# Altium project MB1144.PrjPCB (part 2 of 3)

## Sheet LCD_Glass.SchDoc: LCD_Glass
size A3; DocumentNumber: 6; Revision: C-02; SheetNumber: 6; SheetTotal: 26; PageSetup: Record=PageOptions¦CenterHorizontal=True¦CenterVertical=True¦PrintScale=1.04¦XCorrection=1.00¦YCorrection=1.00¦PrintKind=1¦BorderSize=5000000¦LeftOffset=0¦BottomOffset=0¦Orientation=2¦PaperLength=1000¦PaperWidth=1000¦Scale=100¦PaperSource=7¦PrintQuality=600¦MediaType=1¦DitherType=10¦PaperKind=A3¦PrintScaleMode=1; Project: STM32L476G-EVAL
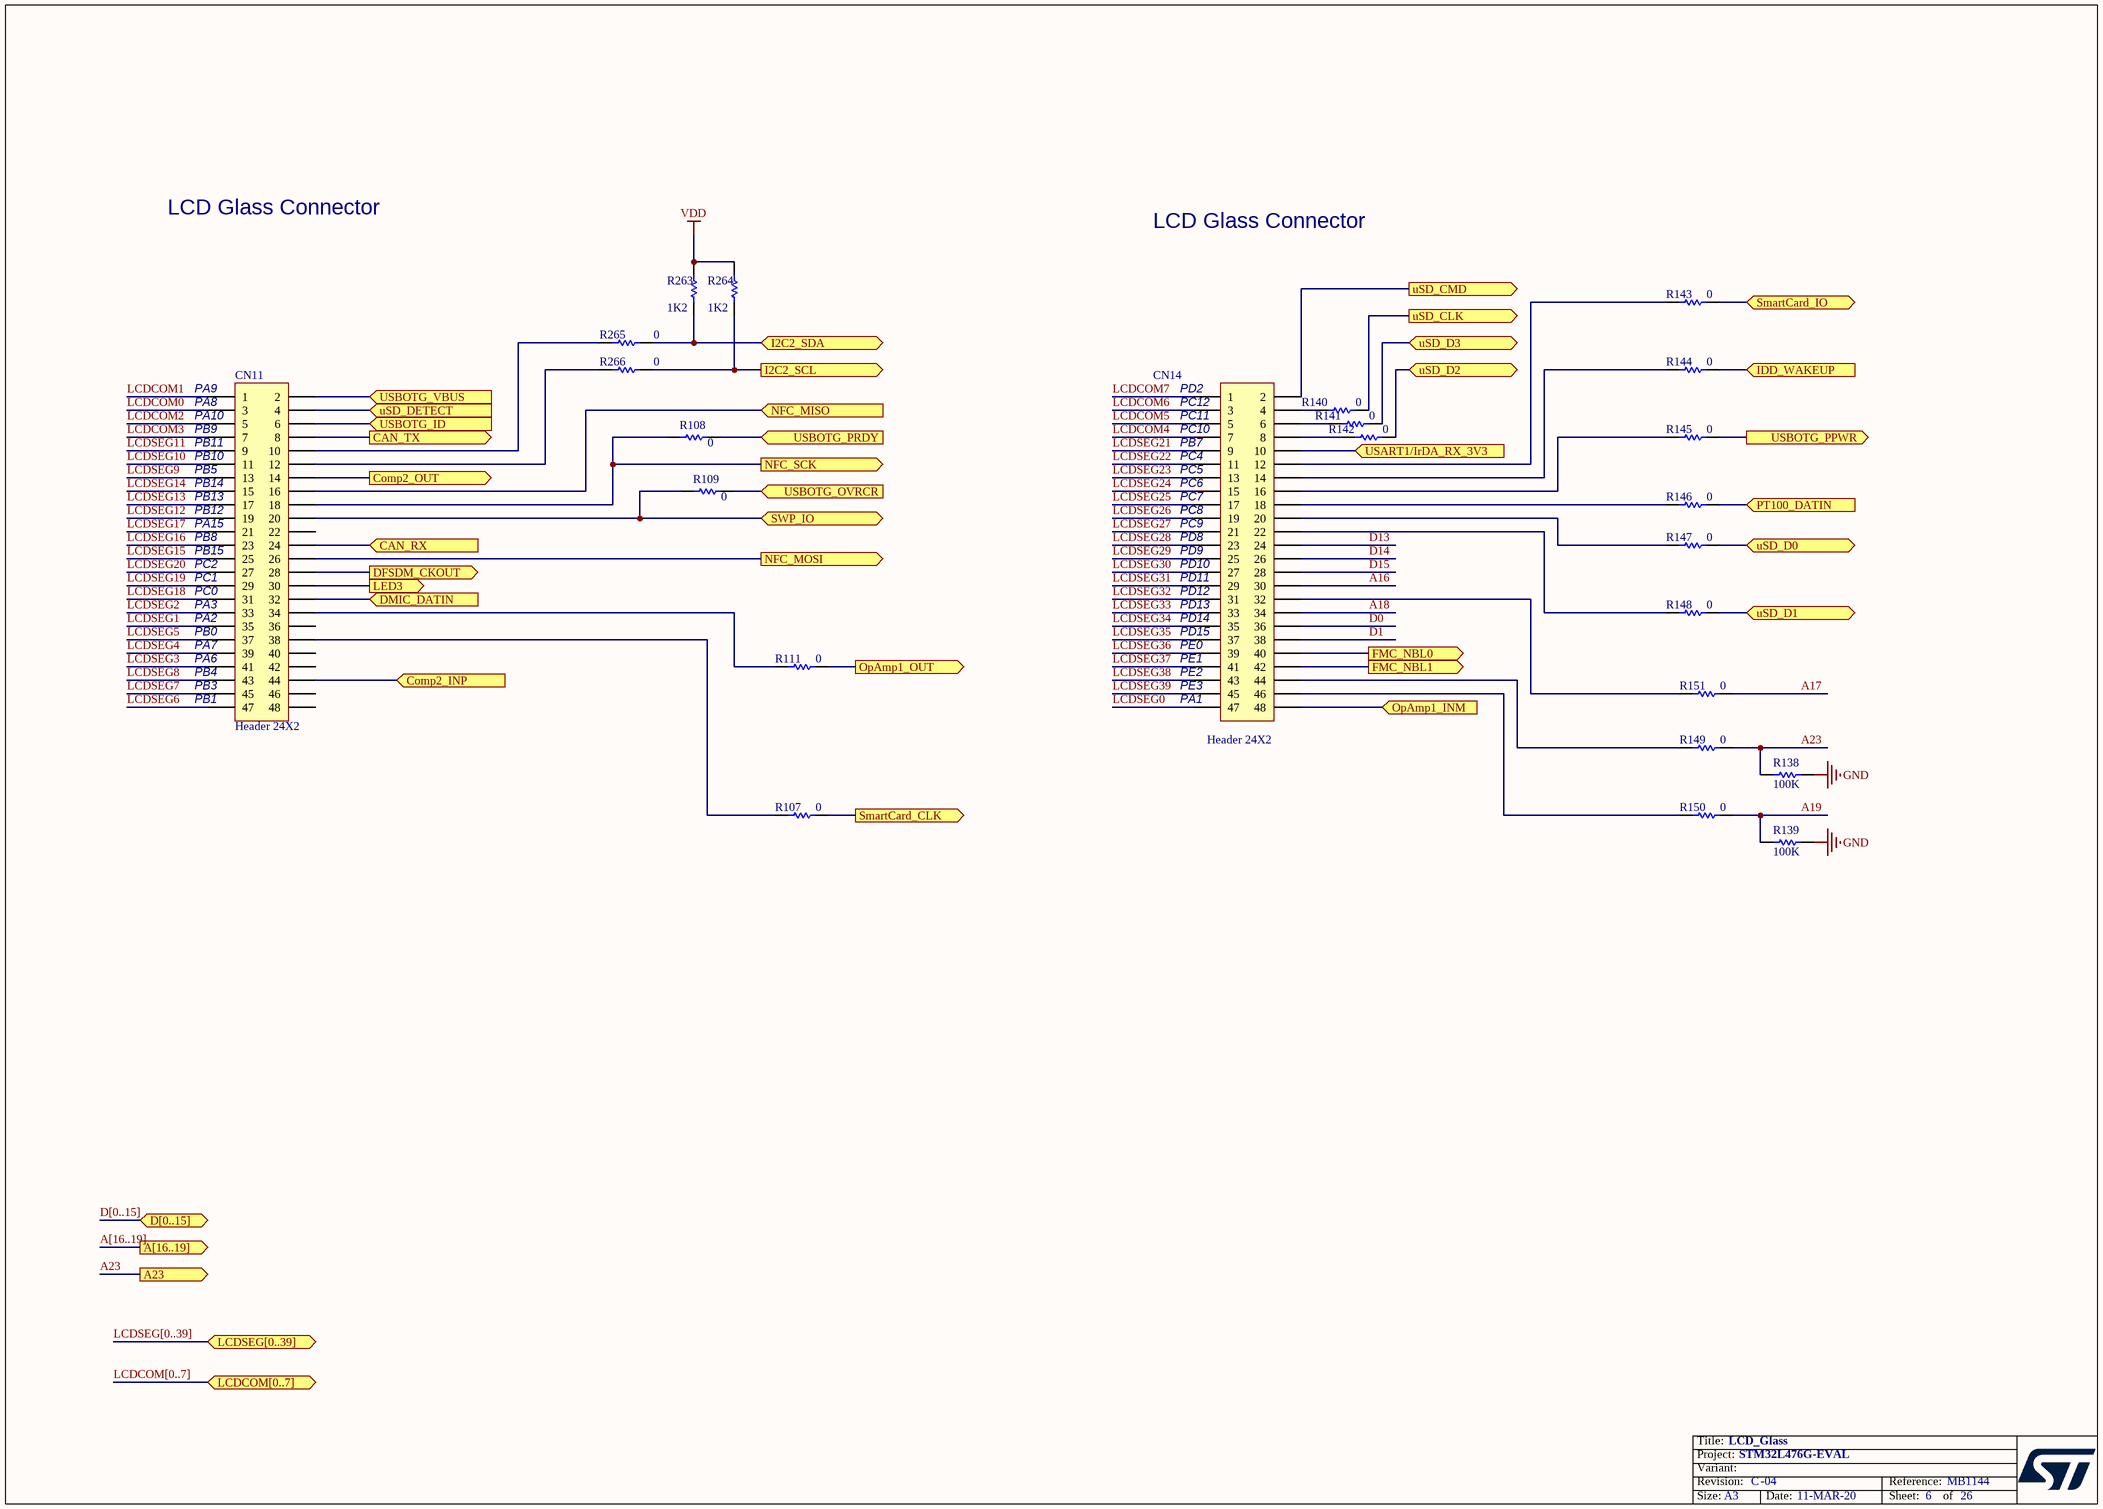
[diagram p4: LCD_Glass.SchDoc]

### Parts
CN11  Header 24X2  [HDR_2X24_2R54]
CN14  Header 24X2  [HDR_2X24_2R54]
R107  0  [0603R]
R108  0  [SB_0603]
R109  0  [SB_0603]
R111  0  [0603R]
R138  100K  [0402R]
R139  100K  [0402R]
R140  0  [0603R]
R141  0  [0603R]
R142  0  [0603R]
R143  0  [0603R]
R144  0  [0603R]
R145  0  [0603R]
R146  0  [0603R]
R147  0  [0603R]
R148  0  [0603R]
R149  0  [0603R]
R150  0  [0603R]
R151  0  [0603R]
R263  1K2  [0402R]
R264  1K2  [0402R]
R265  0  [0603R]
R266  0  [0603R]

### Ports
A23 (out), A[16..19] (out), CAN_RX (in), CAN_TX (out), Comp2_INP (in), Comp2_OUT (out), D[0..15] (bidir), DFSDM_CKOUT (out), DMIC_DATIN (in), FMC_NBL0 (out), FMC_NBL1 (out), I2C2_SCL (out), I2C2_SDA (bidir), IDD_WAKEUP (in), LCDCOM[0..7] (bidir), LCDSEG[0..39] (bidir), LED3 (out), NFC_MISO (in), NFC_MOSI (out), NFC_SCK (out), OpAmp1_INM (in), OpAmp1_OUT (out), PT100_DATIN (in), SmartCard_CLK (out), SmartCard_IO (bidir), SWP_IO (bidir), USART1/IrDA_RX_3V3 (in), USBOTG_ID (in), USBOTG_OVRCR (in), USBOTG_PPWR (out), USBOTG_PRDY (in), USBOTG_VBUS (in), uSD_CLK (out), uSD_CMD (out), uSD_D0 (bidir), uSD_D1 (bidir), uSD_D2 (bidir), uSD_D3 (bidir), uSD_DETECT (in)

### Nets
GND: R138.2 R139.2
VDD: R263.1 R264.1
A16: CN14.30
A17: R151.1
A18: CN14.34
A19: R139.1 R150.1
A23: R138.1 R149.1 ; port A23
Comp2_INP: CN11.44 ; port Comp2_INP
Comp2_OUT: CN11.14 ; port Comp2_OUT
D0: CN14.36
D1: CN14.38
D13: CN14.24
D14: CN14.26
D15: CN14.28
LCDCOM0: CN11.3
LCDCOM1: CN11.1
LCDCOM2: CN11.5
LCDCOM3: CN11.7
LCDCOM4: CN14.7
LCDCOM5: CN14.5
LCDCOM6: CN14.3
LCDCOM7: CN14.1
LCDSEG0: CN14.47
LCDSEG1: CN11.35
LCDSEG2: CN11.33
LCDSEG3: CN11.41
LCDSEG4: CN11.39
LCDSEG5: CN11.37
LCDSEG6: CN11.47
LCDSEG7: CN11.45
LCDSEG8: CN11.43
LCDSEG9: CN11.13
LCDSEG10: CN11.11
LCDSEG11: CN11.9
LCDSEG12: CN11.19
LCDSEG13: CN11.17
LCDSEG14: CN11.15
LCDSEG15: CN11.25
LCDSEG16: CN11.23
LCDSEG17: CN11.21
LCDSEG18: CN11.31
LCDSEG19: CN11.29
LCDSEG20: CN11.27
LCDSEG21: CN14.9
LCDSEG22: CN14.11
LCDSEG23: CN14.13
LCDSEG24: CN14.15
LCDSEG25: CN14.17
LCDSEG26: CN14.19
LCDSEG27: CN14.21
LCDSEG28: CN14.23
LCDSEG29: CN14.25
LCDSEG30: CN14.27
LCDSEG31: CN14.29
LCDSEG32: CN14.31
LCDSEG33: CN14.33
LCDSEG34: CN14.35
LCDSEG35: CN14.37
LCDSEG36: CN14.39
LCDSEG37: CN14.41
LCDSEG38: CN14.43
LCDSEG39: CN14.45
OpAmp1_INM: CN14.48 ; port OpAmp1_INM
OpAmp1_OUT: R111.1 ; port OpAmp1_OUT
NetC15_1: CN11.2 R108.2 ; port USBOTG_VBUS, port USBOTG_PRDY
NetCN11_4: CN11.4 ; port uSD_DETECT
NetCN11_6: CN11.6 ; port USBOTG_ID
NetCN11_8: CN11.8 ; port CAN_TX
NetCN11_10: CN11.10 R265.2
NetCN11_12: CN11.12 R266.2
NetCN11_16: CN11.16 ; port NFC_MISO
NetCN11_18: CN11.18 R108.1 ; port NFC_SCK
NetCN11_20: CN11.20 R109.1 ; port SWP_IO
NetCN11_24: CN11.24 ; port CAN_RX
NetCN11_26: CN11.26 ; port NFC_MOSI
NetCN11_28: CN11.28 ; port DFSDM_CKOUT
NetCN11_30: CN11.30 ; port LED3
NetCN11_32: CN11.32 ; port DMIC_DATIN
NetCN11_34: CN11.34 R111.2
NetCN11_38: CN11.38 R107.2
NetCN14_2: CN14.2 ; port uSD_CMD
NetCN14_4: CN14.4 R140.2
NetCN14_6: CN14.6 R141.2
NetCN14_8: CN14.8 R142.2
NetCN14_10: CN14.10 ; port USART1/IrDA_RX_3V3
NetCN14_12: CN14.12 R143.2
NetCN14_14: CN14.14 R144.2
NetCN14_16: CN14.16 R145.2
NetCN14_18: CN14.18 R146.2
NetCN14_20: CN14.20 R147.2
NetCN14_22: CN14.22 R148.2
NetCN14_32: CN14.32 R151.2
NetCN14_40: CN14.40 ; port FMC_NBL0
NetCN14_42: CN14.42 ; port FMC_NBL1
NetCN14_44: CN14.44 R149.2
NetCN14_46: CN14.46 R150.2
NetCN18_1: R142.1 ; port uSD_D2
NetCN18_2: R141.1 ; port uSD_D3
NetCN18_5: R140.1 ; port uSD_CLK
NetCN18_7: R147.1 ; port uSD_D0
NetCN18_8: R148.1 ; port uSD_D1
NetJP19_1: R145.1 ; port USBOTG_PPWR
NetLD6_2: R109.2 ; port USBOTG_OVRCR
NetR24_1: R146.1 ; port PT100_DATIN
NetR107_1: R107.1 ; port SmartCard_CLK
NetR137_1: R144.1 ; port IDD_WAKEUP
NetR143_1: R143.1 ; port SmartCard_IO
NetR263_2: R263.2 R265.1 ; port I2C2_SDA
NetR264_2: R264.2 R266.1 ; port I2C2_SCL

Not connected (* = marked no-connect by the designer): CN11 22 36 40 42 46 48

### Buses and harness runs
bus A[16..19] = port A[16..19]
bus D[0..15] = port D[0..15]
bus LCDCOM[0..7] = port LCDCOM[0..7]
bus LCDSEG[0..39] = port LCDSEG[0..39]

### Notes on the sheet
- LCD Glass Connector
- (near CN11) PA9
- (near CN11) PA8
- (near CN11) PA10
- (near CN11) PB9
- (near CN11) PB11
- (near CN14) PD2
- (near CN14) PC12
- (near CN14) PC11
- (near CN14) PC10
- (near CN14) PB7
- (near CN11) PB10
- (near CN11) PB5
- (near CN11) PB14
- (near CN11) PB13
- (near CN11) PB12
- (near CN14) PC4
- (near CN14) PC5
- (near CN14) PC6
- (near CN14) PC7
- (near CN14) PC
- (near CN14) PC8
- (near CN11) PA15
- (near CN11) PB8
- (near CN11) PB15
- (near CN11) PC2
- (near CN11) PC1
- (near CN14) PD11
- (near CN14) PD10
- (near CN14) PD9
- (near CN14) PD8
- (near CN14) PC9
- (near CN11) PA3
- (near CN11) PA2
- (near CN11) PA7
- (near CN11) PB0
- (near CN11) PC0
- (near CN14) PD12
- (near CN14) PD13
- (near CN14) PD14
- (near CN14) PD15
- (near CN14) PE0
- (near CN11) PA6
- (near CN11) PB4
- (near CN11) PB3
- (near CN11) PB1
- (near CN14) PE1
- (near CN14) PE2
- (near CN14) PE3
- (near CN14) PA1

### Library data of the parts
CN11 CN14 = Header 24X2: Header, 24-Pin, Dual row; Ordered by: Subcon; Comments: LCD Glass connector; ECCN_US/EU: NA; Assembly: with MB979
R107 R111 R138-R151 = res1: Resistor; Value: 1K; Ordered by: Subcon; ECCN_US/EU: NA
R108 R109 R263-R266 = Res1: Resistor; Value: 1K; Ordered by: Subcon; ECCN_US/EU: NA

## Sheet IO_Expandor.SchDoc: IO_Expandor
size A4; DocumentNumber: 16; Revision: C-02; SheetNumber: 16; SheetTotal: 26; Project: STM32L476G-EVAL
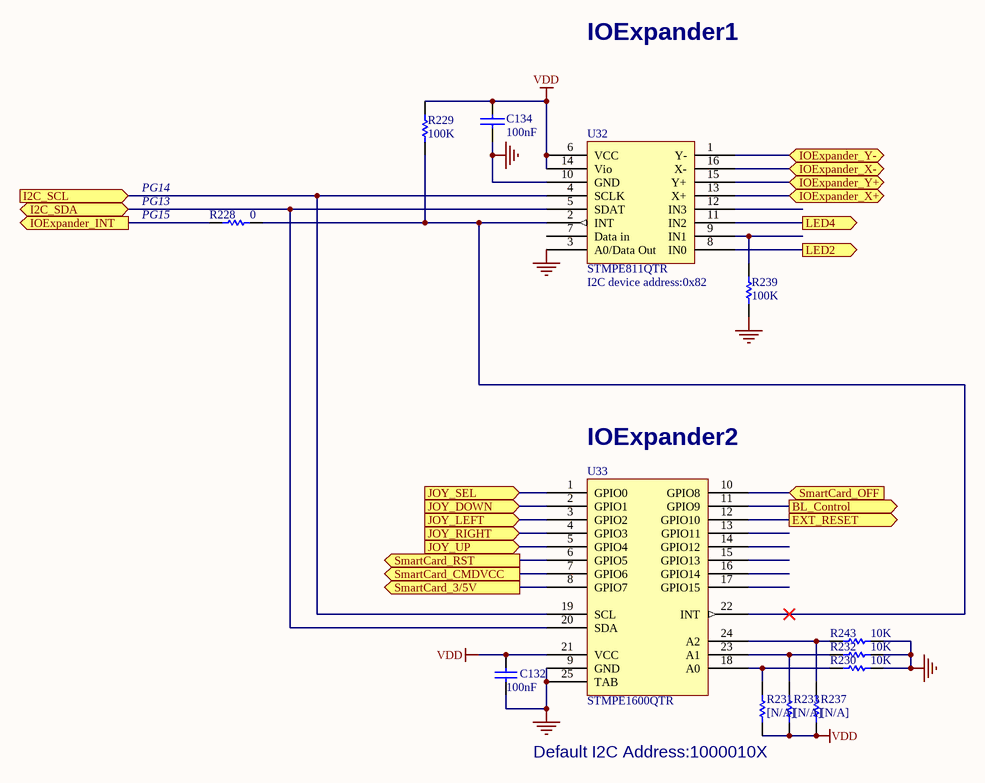
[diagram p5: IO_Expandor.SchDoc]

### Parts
C132  100nF  [0402C]
C134  100nF  [0402C]
R228  0  [0603R]
R229  100K  [0402R]
R230  10K  [0402R]
R231  [N/A]  [0603R]
R232  10K  [0402R]
R233  [N/A]  [0603R]
R237  [N/A]  [0603R]
R239  100K  [0402R]
R243  10K  [0402R]
U32  STMPE811QTR  [QFN16_0R5_3X3]
U33  STMPE1600QTR  [QFN24_0R5_4X4]

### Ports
BL_Control (out), EXT_RESET (out), I2C_SCL (in), I2C_SDA (bidir), IOExpander_INT (out), IOExpander_X+ (bidir), IOExpander_X- (bidir), IOExpander_Y+ (bidir), IOExpander_Y- (bidir), JOY_DOWN (in), JOY_LEFT (in), JOY_RIGHT (in), JOY_SEL (in), JOY_UP (in), LED2 (out), LED4 (out), SmartCard_3/5V (out), SmartCard_CMDVCC (out), SmartCard_OFF (in), SmartCard_RST (out)

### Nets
GND: C132.2 C134.2 R230.1 R232.1 R239.2 R243.1 U32.3(A0/Data_Out) U32.10(GND) U33.9(GND) U33.25(TAB)
VDD: C132.1 C134.1 R229.1 R231.1 R233.1 R237.1 U32.6(VCC) U32.14(Vio) U33.21(VCC)
I2C_SCL: U32.4(SCLK) U33.19(SCL) ; port I2C_SCL
I2C_SDA: U32.5(SDAT) U33.20(SDA) ; port I2C_SDA
PG15: R228.1 ; port IOExpander_INT
NetB3_1: U33.3(GPIO2) ; port JOY_LEFT
NetB3_2: U33.1(GPIO0) ; port JOY_SEL
NetB3_3: U33.2(GPIO1) ; port JOY_DOWN
NetB3_4: U33.4(GPIO3) ; port JOY_RIGHT
NetB3_6: U33.5(GPIO4) ; port JOY_UP
NetCN3_4: U33.12(GPIO10) ; port EXT_RESET
NetCN19_31: U32.16(X-) ; port IOExpander_X-
NetCN19_32: U32.13(X+) ; port IOExpander_X+
NetCN19_33: U32.1(Y-) ; port IOExpander_Y-
NetCN19_34: U32.15(Y+) ; port IOExpander_Y+
NetR213_1: U33.10(GPIO8) ; port SmartCard_OFF
NetR214_2: U33.6(GPIO5) ; port SmartCard_RST
NetR215_2: U33.7(GPIO6) ; port SmartCard_CMDVCC
NetR228_2: R228.2 R229.2 U32.2(INT) U33.22(INT)
NetR230_2: R230.2 R231.2 U33.18(A0)
NetR232_2: R232.2 R233.2 U33.23(A1)
NetR237_2: R237.2 R243.2 U33.24(A2)
NetR239_1: R239.1 U32.9(IN1)
NetR241_1: U33.8(GPIO7) ; port SmartCard_3/5V
NetR255_1: U32.11(IN2) ; port LED4
NetR257_1: U32.8(IN0) ; port LED2
NetR260_1: U33.11(GPIO9) ; port BL_Control

Not connected (* = marked no-connect by the designer): U32 7(Data_in) 12(IN3); U33 13(GPIO11) 14(GPIO12) 15(GPIO13) 16(GPIO14) 17(GPIO15)

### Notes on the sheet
- IOExpander1
- PG13
- PG14
- PG15
- I2C device address:0x82
- (near U33) IOExpander2
- Default I2C Address:1000010X

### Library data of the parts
C132 = Cap: Capacitor; Value: 10nF; Ordered by: Subcon; ECCN_US/EU: NA
C134 = CAP: Capacitor; Ordered by: Subcon; ECCN_US/EU: NA
R228 R229 R239 = Res1: as R108 on sheet LCD_Glass
R230 R232 R243 = res1: as R107 on sheet LCD_Glass
R231 R233 R237 = Res1: Resistor; Value: 1K; Ordered by: Subcon; ECCN_US/EU: NA; Fitted: NO
U32 = STMPE811: Ordered by: ST; ECCN_US/EU: EAR99/NEC; Ref St: 9177945
U33 = STMPE1600: Ordered by: ST; ECCN_US/EU: EAR99/NEC; Ref St: 9177976

## Sheet MCU2.SchDoc: MCU2
size A3; DocumentNumber: 4; Revision: C-02; SheetNumber: 4; SheetTotal: 26; PageSetup: Record=PageOptions¦CenterHorizontal=True¦CenterVertical=True¦PrintScale=1.04¦XCorrection=1.00¦YCorrection=1.00¦PrintKind=1¦BorderSize=5000000¦LeftOffset=0¦BottomOffset=0¦Orientation=2¦PaperLength=1000¦PaperWidth=1000¦Scale=100¦PaperSource=7¦PrintQuality=600¦MediaType=1¦DitherType=10¦PaperKind=A3¦PrintScaleMode=1; Project: STM32L476G-EVAL
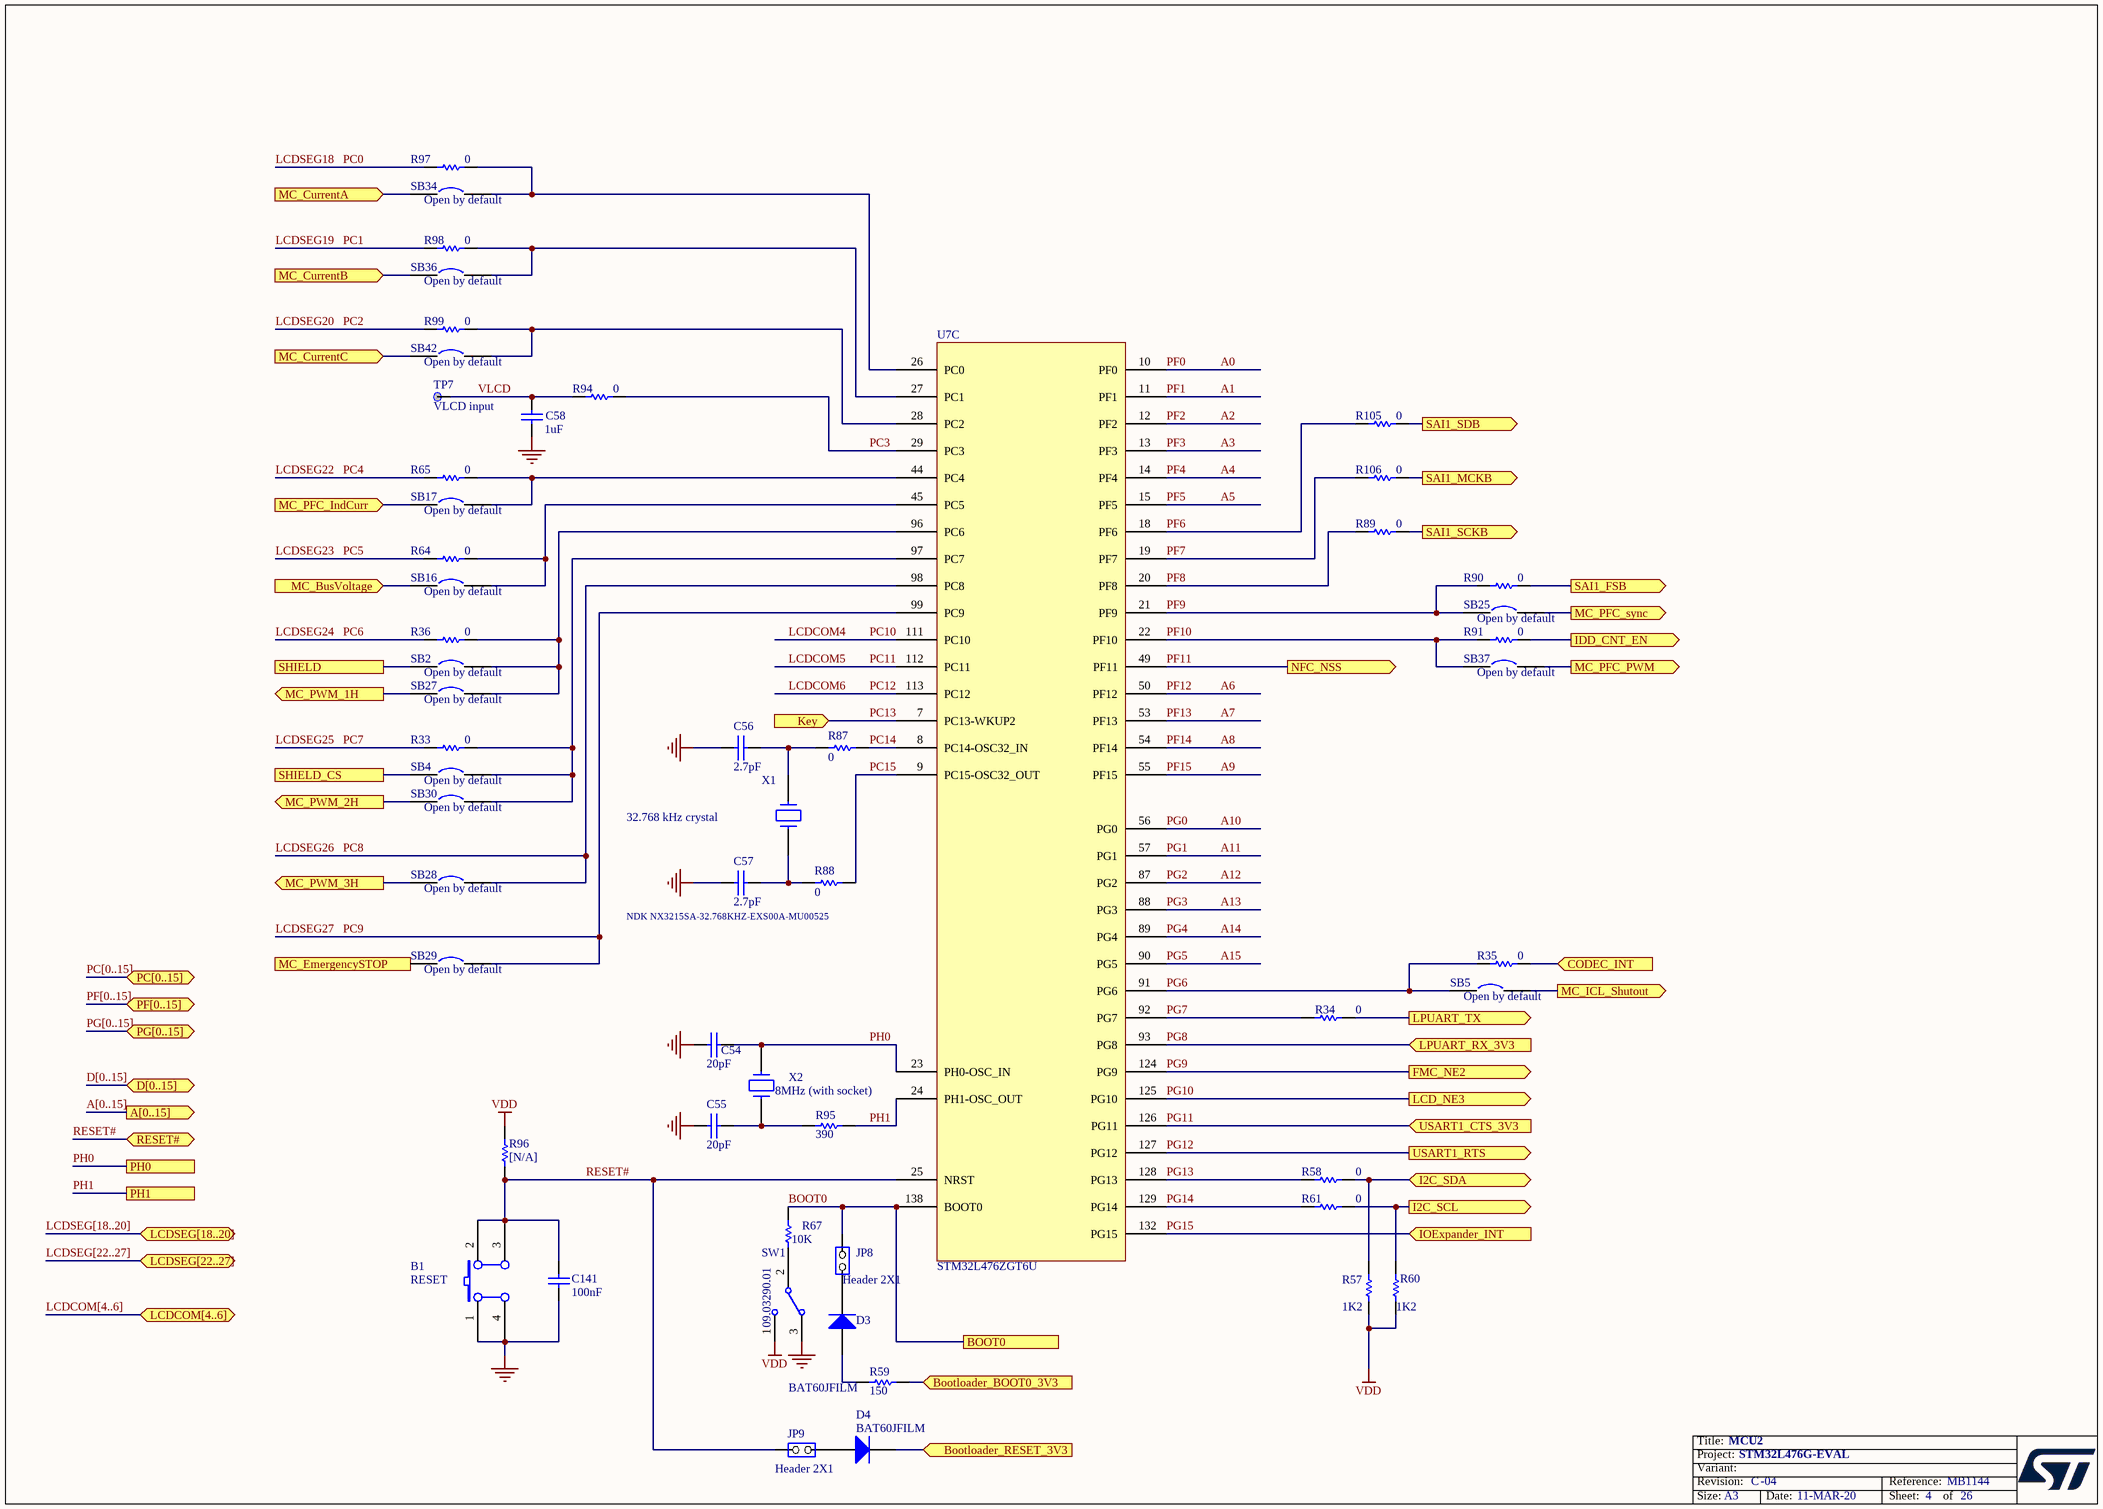
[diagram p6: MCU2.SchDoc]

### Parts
B1  RESET  [PB10]
C54  20pF  [0402R]
C55  20pF  [0402R]
C56  2.7pF  [0603C]
C57  2.7pF  [0603C]
C58  1uF  [0603C]
C141  100nF  [0402C]
D3  BAT60JFILM  [SOD-323]
D4  BAT60JFILM  [SOD-323]
JP8  Header 2X1  [SIP2]
JP9  Header 2X1  [SIP2]
R33  0  [SB_0603]
R34  0  [0603R]
R35  0  [SB_0603]
R36  0  [SB_0603]
R57  1K2  [0402R]
R58  0  [0603R]
R59  150  [0402R]
R60  1K2  [0402R]
R61  0  [0603R]
R64  0  [SB_0603]
R65  0  [SB_0603]
R67  10K  [0402R]
R87  0  [0603R]
R88  0  [0603R]
R89  0  [0603R]
R90  0  [SB_0603]
R91  0  [SB_0603]
R94  0  [0603R]
R95  390  [0603R]
R96  [N/A]  [0603R]
R97  0  [SB_0603]
R98  0  [SB_0603]
R99  0  [SB_0603]
R105  0  [0603R]
R106  0  [0603R]
SB2  Open by default  [SB_0603]
SB4  Open by default  [SB_0603]
SB5  Open by default  [SB_0603]
SB16  Open by default  [SB_0603]
SB17  Open by default  [SB_0603]
SB25  Open by default  [SB_0603]
SB27  Open by default  [SB_0603]
SB28  Open by default  [SB_0603]
SB29  Open by default  [SB_0603]
SB30  Open by default  [SB_0603]
SB34  Open by default  [SB_0603]
SB36  Open by default  [SB_0603]
SB37  Open by default  [SB_0603]
SB42  Open by default  [SB_0603]
SW1  09.03290.01  [SW1_3TH_2R54_10X2R5]
TP7  TP Name: VLCD input  [TP]  (hidden comment: [N/A])
U7  STM32L476ZGT6U  [TQFP144_0R5_22X22_SOCKET]  (part C of 3)
X1  NDK NX3215SA-32.768KHZ-EXS00A-MU00525  [XTAL_2SM_3R2X1R5]
X2  8MHz (with socket)  [XTAL_SOCKET]

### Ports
A[0..15] (out), BOOT0, Bootloader_BOOT0_3V3 (in), Bootloader_RESET_3V3 (in), CODEC_INT (in), D[0..15] (bidir), FMC_NE2 (out), I2C_SCL (out), I2C_SDA (bidir), IDD_CNT_EN (out), IOExpander_INT (in), Key (in), LCD_NE3 (out), LCDCOM[4..6] (bidir), LCDSEG[18..20] (bidir), LCDSEG[22..27] (bidir), LPUART_RX_3V3 (in), LPUART_TX (out), MC_BusVoltage (in), MC_CurrentA (in), MC_CurrentB (in), MC_CurrentC (in), MC_EmergencySTOP (in), MC_ICL_Shutout (out), MC_PFC_IndCurr (in), MC_PFC_PWM (out), MC_PFC_sync (out), MC_PWM_1H (out), MC_PWM_2H (out), MC_PWM_3H (out), NFC_NSS (out), PC[0..15] (bidir), PF[0..15] (bidir), PG[0..15] (bidir), PH0, PH1, RESET# (bidir), SAI1_FSB (out), SAI1_MCKB (out), SAI1_SCKB (out), SAI1_SDB (out), SHIELD, SHIELD_CS, USART1_CTS_3V3 (in), USART1_RTS (out)

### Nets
GND: B1.1(A0) B1.4(A1) C54.2 C55.2 C56.2 C57.2 C58.1 C141.1 SW1.3
VDD: R57.2 R60.2 R96.2 SW1.1
A0: U7.10(PF0)  [also labelled PF0]
A1: U7.11(PF1)  [also labelled PF1]
A2: U7.12(PF2)  [also labelled PF2]
A3: U7.13(PF3)  [also labelled PF3]
A4: U7.14(PF4)  [also labelled PF4]
A5: U7.15(PF5)  [also labelled PF5]
A6: U7.50(PF12)  [also labelled PF12]
A7: U7.53(PF13)  [also labelled PF13]
A8: U7.54(PF14)  [also labelled PF14]
A9: U7.55(PF15)  [also labelled PF15]
A10: U7.56(PG0)  [also labelled PG0]
A11: U7.57(PG1)  [also labelled PG1]
A12: U7.87(PG2)  [also labelled PG2]
A13: U7.88(PG3)  [also labelled PG3]
A14: U7.89(PG4)  [also labelled PG4]
A15: U7.90(PG5)  [also labelled PG5]
BOOT0: JP8.1(COMMON) R67.1 U7.138(BOOT0) ; port BOOT0
I2C_SCL: R60.1 R61.1 ; port I2C_SCL
I2C_SDA: R57.1 R58.1 ; port I2C_SDA
LCDCOM4: U7.111(PC10)  [also labelled PC10]
LCDCOM5: U7.112(PC11)  [also labelled PC11]
LCDCOM6: U7.113(PC12)  [also labelled PC12]
LCDSEG18: R97.1  [also labelled PC0]
LCDSEG19: R98.1  [also labelled PC1]
LCDSEG20: R99.1  [also labelled PC2]
LCDSEG22: R65.1  [also labelled PC4]
LCDSEG23: R64.1  [also labelled PC5]
LCDSEG24: R36.1  [also labelled PC6]
LCDSEG25: R33.1  [also labelled PC7]
LCDSEG26: SB28.2 U7.98(PC8)  [also labelled PC8]
LCDSEG27: SB29.2 U7.99(PC9)  [also labelled PC9]
PC3: R94.1 U7.29(PC3)
PC13: U7.7(PC13-WKUP2) ; port Key
PC14: R87.2 U7.8(PC14-OSC32_IN)
PC15: R88.2 U7.9(PC15-OSC32_OUT)
PF6: R105.2 U7.18(PF6)
PF7: R106.2 U7.19(PF7)
PF8: R89.2 U7.20(PF8)
PF9: R90.2 SB25.1 U7.21(PF9)
PF10: R91.2 SB37.1 U7.22(PF10)
PF11: U7.49(PF11) ; port NFC_NSS
PG6: R35.2 SB5.1 U7.91(PG6)
PG7: R34.2 U7.92(PG7)
PG8: U7.93(PG8) ; port LPUART_RX_3V3
PG9: U7.124(PG9) ; port FMC_NE2
PG10: U7.125(PG10) ; port LCD_NE3  [project net LCD_NE3]
PG11: U7.126(PG11) ; port USART1_CTS_3V3
PG12: U7.127(PG12) ; port USART1_RTS
PG13: R58.2 U7.128(PG13)
PG14: R61.2 U7.129(PG14)
PG15: U7.132(PG15) ; port IOExpander_INT
PH0: C54.1 U7.23(PH0-OSC_IN) X2.2 ; port PH0
PH1: R95.1 U7.24(PH1-OSC_OUT) ; port PH1
RESET#: B1.2(B0) B1.3(B1) C141.2 JP9.1(COMMON) R96.1 U7.25(NRST) ; port RESET#
VLCD: C58.2 R94.2 TP7.1
NetC3_1: SB17.1 ; port MC_PFC_IndCurr
NetC7_2: SB29.1 ; port MC_EmergencySTOP
NetC9_2: SB37.2 ; port MC_PFC_PWM
NetC10_2: SB42.1 ; port MC_CurrentC
NetC11_1: SB16.1 ; port MC_BusVoltage
NetC13_2: SB36.1 ; port MC_CurrentB
NetC14_2: SB34.1 ; port MC_CurrentA
NetC16_2: SB25.2 ; port MC_PFC_sync
NetC34_2: SB4.1 ; port SHIELD_CS
NetC55_1: C55.1 R95.2 X2.1
NetC56_1: C56.1 R87.1 X1.2
NetC57_1: C57.1 R88.1 X1.1
NetCN2_3: SB27.1 ; port MC_PWM_1H
NetCN2_7: SB30.1 ; port MC_PWM_2H
NetCN2_11: SB28.1 ; port MC_PWM_3H
NetCN2_21: SB5.2 ; port MC_ICL_Shutout
NetD3_1: D3.1(A) R59.1
NetD3_2: D3.2(K) JP8.2(NO)
NetD4_1: D4.1(A) JP9.2(NO)
NetD4_2: D4.2(K) ; port Bootloader_RESET_3V3
NetR33_2: R33.2 SB4.2 SB30.2 U7.97(PC7)
NetR34_1: R34.1 ; port LPUART_TX
NetR35_1: R35.1 ; port CODEC_INT
NetR36_2: R36.2 SB2.2 SB27.2 U7.96(PC6)
NetR37_1: SB2.1 ; port SHIELD
NetR59_2: R59.2 ; port Bootloader_BOOT0_3V3
NetR64_2: R64.2 SB16.2 U7.45(PC5)
NetR65_2: R65.2 SB17.2 U7.44(PC4)
NetR67_2: R67.2 SW1.2
NetR89_1: R89.1 ; port SAI1_SCKB
NetR90_1: R90.1 ; port SAI1_FSB
NetR91_1: R91.1 ; port IDD_CNT_EN
NetR97_2: R97.2 SB34.2 U7.26(PC0)
NetR98_2: R98.2 SB36.2 U7.27(PC1)
NetR99_2: R99.2 SB42.2 U7.28(PC2)
NetR105_1: R105.1 ; port SAI1_SDB
NetR106_1: R106.1 ; port SAI1_MCKB

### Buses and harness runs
bus A[0..15] = port A[0..15]
bus D[0..15] = port D[0..15]
bus LCDCOM[4..6] = port LCDCOM[4..6]
bus LCDSEG[18..20] = port LCDSEG[18..20]
bus LCDSEG[22..27] = port LCDSEG[22..27]
bus PC[0..15] = port PC[0..15]
bus PF[0..15] = port PF[0..15]
bus PG[0..15] = port PG[0..15]

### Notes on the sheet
- 32.768 kHz crystal

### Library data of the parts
B1 = SW PUSHBUTTON: SE PUSHBUTTON; Ordered by: Subcon; Comments: no comment; Assembly: Black; ECCN_US/EU: NA
C54-C57 = CAP: as C134 on sheet IO_Expandor
C58 = CAP: Capacitor; Value: 100nF; Ordered by: Subcon; ECCN_US/EU: NA
C141 = CAP: Capacitor; Value: 100pF; Ordered by: Subcon; ECCN_US/EU: NA
D3 D4 = Diode: Default Diode; Code - JEDEC: DO-214-AB; Ordered by: ST; ECCN_US/EU: EAR99/NEC; Ref St: 9151097
JP8 JP9 = JP2: Ordered by: Subcon; ECCN_US/EU: NA
R33 R34 R36 R57 R58 R60 R61 R64 R65 R87 R88 R95 R97-R99 = Res1: as R108 on sheet LCD_Glass
R35 R59 R67 R89-R91 R94 R105 R106 = res1: as R107 on sheet LCD_Glass
R96 = res1: Resistor; Value: 1K; Ordered by: Subcon; ECCN_US/EU: NA; Fitted: NO
SB2 SB4 SB5 SB16 SB17 SB25 SB27-SB30 SB34 SB36 SB37 SB42 = Circuit Breaker: Ordered by: Subcon; Comments: Solder bridge; Fitted: NO; ECCN_US/EU: NA
SW1 = SW-SPDT: SPDT Subminiature Toggle Switch, Right Angle Mounting, Vertical Actuation; Revision 1: Jul-2002: Re-released for DXP Platform.; Revision 2: 17-Dec-2003: Schematic revised, PCB Footprint replaced.; Ordered by: Subcon; ECCN_US/EU: NA
TP7 = TP: Ordered by: Subcon; Fitted or not fitted: NO; ECCN_US/EU: NA; Fitted: NO
U7 = STM32L476_TQFP144: Manuf_Part_1: STM32L476ZGT6U cut1.3; Ordered by: ST; ECCN_US/EU: 3A991A2/NEC; Assembly: MCU; Ref St: 9175195
X1 = CRYSTAL_32K: Crystal; Ordered by: ST; ECCN_US/EU: NA
X2 = CRYSTAL: Manuf_1: jfvny; Manuf_Part_1: HC-49S-C16QSA-8M; Ordered by: Subcon; ECCN_US/EU: NA

## Sheet SRAM&Flash.SchDoc: SRAM&Flash
size A4; DocumentNumber: 19; Revision: C-02; SheetNumber: 19; SheetTotal: 26; Project: STM32L476G-EVAL
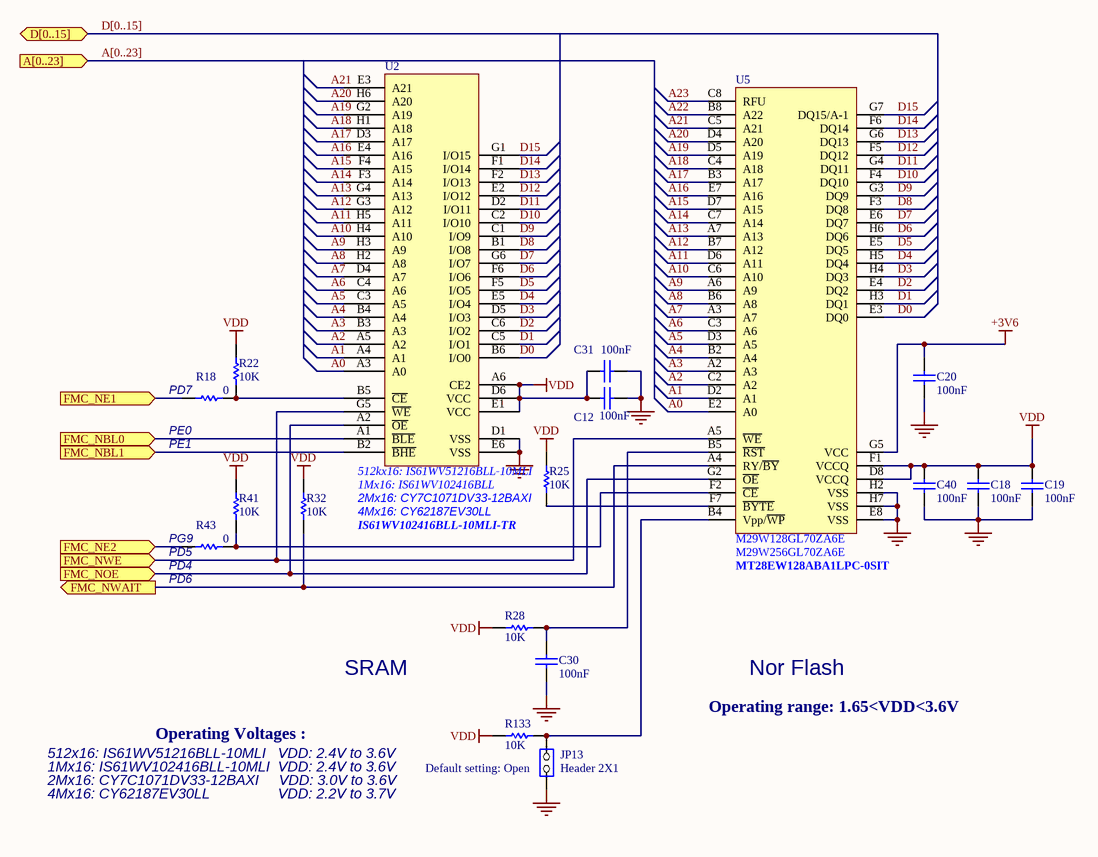
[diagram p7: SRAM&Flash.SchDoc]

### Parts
C12  100nF  [0402C]
C18  100nF  [0402C]
C19  100nF  [0402C]
C20  100nF  [0402C]
C30  100nF  [0402C]
C31  100nF  [0402C]
C40  100nF  [0402C]
JP13  Header 2X1  [SIP2]
R18  0  [0603R]
R22  10K  [0402R]
R25  10K  [0402R]
R28  10K  [0402R]
R32  10K  [0402R]
R41  10K  [0402R]
R43  0  [0603R]
R133  10K  [0402R]
U2  IS61WV102416BLL-10MLI-TR  [BGA48_0R75_9X11]
U5  value MT28EW128ABA1LPC-0SIT  [ICC_FBGA64_11X13_P1]  (hidden comment: PC28F128M29EWLA)

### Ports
A[0..23] (in), D[0..15] (bidir), FMC_NBL0 (in), FMC_NBL1 (in), FMC_NE1 (in), FMC_NE2 (in), FMC_NOE (in), FMC_NWAIT (out), FMC_NWE (in)

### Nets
+3V6: C20.1 U5.G5(VCC)
GND: C12.2 C18.2 C19.2 C20.2 C30.2 C31.2 C40.2 JP13.1(COMMON) U2.D1(VSS) U2.E6(VSS) U5.E8(VSS) U5.H2(VSS) U5.H7(VSS)
VDD: C12.1 C18.1 C19.1 C31.1 C40.1 R22.1 R25.1 R28.1 R32.1 R41.1 R133.1 U2.A6(CE2) U2.D6(VCC) U2.E1(VCC) U5.D8(VCCQ) U5.F1(VCCQ)
A0: U2.A3(A0) U5.E2(A0)
A1: U2.A4(A1) U5.D2(A1)
A2: U2.A5(A2) U5.C2(A2)
A3: U2.B3(A3) U5.A2(A3)
A4: U2.B4(A4) U5.B2(A4)
A5: U2.C3(A5) U5.D3(A5)
A6: U2.C4(A6) U5.C3(A6)
A7: U2.D4(A7) U5.A3(A7)
A8: U2.H2(A8) U5.B6(A8)
A9: U2.H3(A9) U5.A6(A9)
A10: U2.H4(A10) U5.C6(A10)
A11: U2.H5(A11) U5.D6(A11)
A12: U2.G3(A12) U5.B7(A12)
A13: U2.G4(A13) U5.A7(A13)
A14: U2.F3(A14) U5.C7(A14)
A15: U2.F4(A15) U5.D7(A15)
A16: U2.E4(A16) U5.E7(A16)
A17: U2.D3(A17) U5.B3(A17)
A18: U2.H1(A18) U5.C4(A18)
A19: U2.G2(A19) U5.D5(A19)
A20: U2.H6(A20) U5.D4(A20)
A21: U2.E3(A21) U5.C5(A21)
A22: U5.B8(A22)
A23: U5.C8(RFU)
D0: U2.B6(I/O0) U5.E3(DQ0)
D1: U2.C5(I/O1) U5.H3(DQ1)
D2: U2.C6(I/O2) U5.E4(DQ2)
D3: U2.D5(I/O3) U5.H4(DQ3)
D4: U2.E5(I/O4) U5.H5(DQ4)
D5: U2.F5(I/O5) U5.E5(DQ5)
D6: U2.F6(I/O6) U5.H6(DQ6)
D7: U2.G6(I/O7) U5.E6(DQ7)
D8: U2.B1(I/O8) U5.F3(DQ8)
D9: U2.C1(I/O9) U5.G3(DQ9)
D10: U2.C2(I/O10) U5.F4(DQ10)
D11: U2.D2(I/O11) U5.G4(DQ11)
D12: U2.E2(I/O12) U5.F5(DQ12)
D13: U2.F2(I/O13) U5.G6(DQ13)
D14: U2.F1(I/O14) U5.F6(DQ14)
D15: U2.G1(I/O15) U5.G7(DQ15/A-1)
PD4: U2.A2(~{OE}) U5.G2(~{OE}) ; port FMC_NOE
PD5: U2.G5(~{WE}) U5.A5(~{WE}) ; port FMC_NWE
PD7: R18.2 ; port FMC_NE1
PG9: R43.2 ; port FMC_NE2
NetC30_1: C30.1 R28.2 U5.B5(~{RST})
NetCN14_40: U2.A1(~{BLE}) ; port FMC_NBL0
NetCN14_42: U2.B2(~{BHE}) ; port FMC_NBL1
NetJP13_2: JP13.2(NO) R133.2 U5.B4(Vpp/~{WP})
NetR18_1: R18.1 R22.2 U2.B5(~{CE})
NetR25_2: R25.2 U5.F7(~{BYTE})
NetR32_2: R32.2 U5.A4(RY/~{BY}) ; port FMC_NWAIT
NetR41_2: R41.2 R43.1 U5.F2(~{CE})

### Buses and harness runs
bus A[0..23] = port A[0..23]
bus D[0..15] = port D[0..15]

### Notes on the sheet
- (near R18) PD7
- PE1
- (near R18) PE0
- 512kx16: IS61WV51216BLL-10MLI
- (near U2) 1Mx16: IS61WV102416BLL
- (near R43) PD5
- (near R43) PG9
- 2Mx16: CY7C1071DV33-12BAXI
- 4Mx16: CY62187EV30LL
- (near U5) M29W128GL70ZA6E
- (near U5) M29W256GL70ZA6E
- (near R43) PD6
- (near R43) PD4
- SRAM
- Nor Flash
- 512x16: IS61WV51216BLL-10MLI   VDD: 2.4V to 3.6V
- Operating Voltages :
- Operating range: 1.65<VDD<3.6V
- 2Mx16: CY7C1071DV33-12BAXI     VDD: 3.0V to 3.6V
- 4Mx16: CY62187EV30LL                 VDD: 2.2V to 3.7V
- 1Mx16: IS61WV102416BLL-10MLI  VDD: 2.4V to 3.6V
- (near JP13) Default setting: Open

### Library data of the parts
C12 C18-C20 C30 C31 C40 = Cap: as C132 on sheet IO_Expandor
JP13 = JP2: Ordered by: Subcon; ECCN_US/EU: NA
R18 R43 = Res1: as R108 on sheet LCD_Glass
R22 R25 R28 R32 R41 R133 = res1: as R107 on sheet LCD_Glass
U2 = SRAM_4Mx16: Manuf_1: ISSI; Manuf_Part_1: IS61WV102416ALL; Comments: 1Mx16 ISSI SRAM; Ordered by: Subcon; ECCN_US/EU: EAR99/NEC
U5 = MCD-01345: NOR FLASH 128Mbit 75ns - 64-ball LBGA (replacing PC28F128M29EWLA); BMS_Part_Number: 9171980; Part_Type: IC; Part_Preference: Recommended; Manufacturer: MICRON

## Sheet MotorControl.SchDoc: MotorControl
size A4; DocumentNumber: 17; Revision: C-02; SheetNumber: 17; SheetTotal: 26; Project: STM32L476G-EVAL
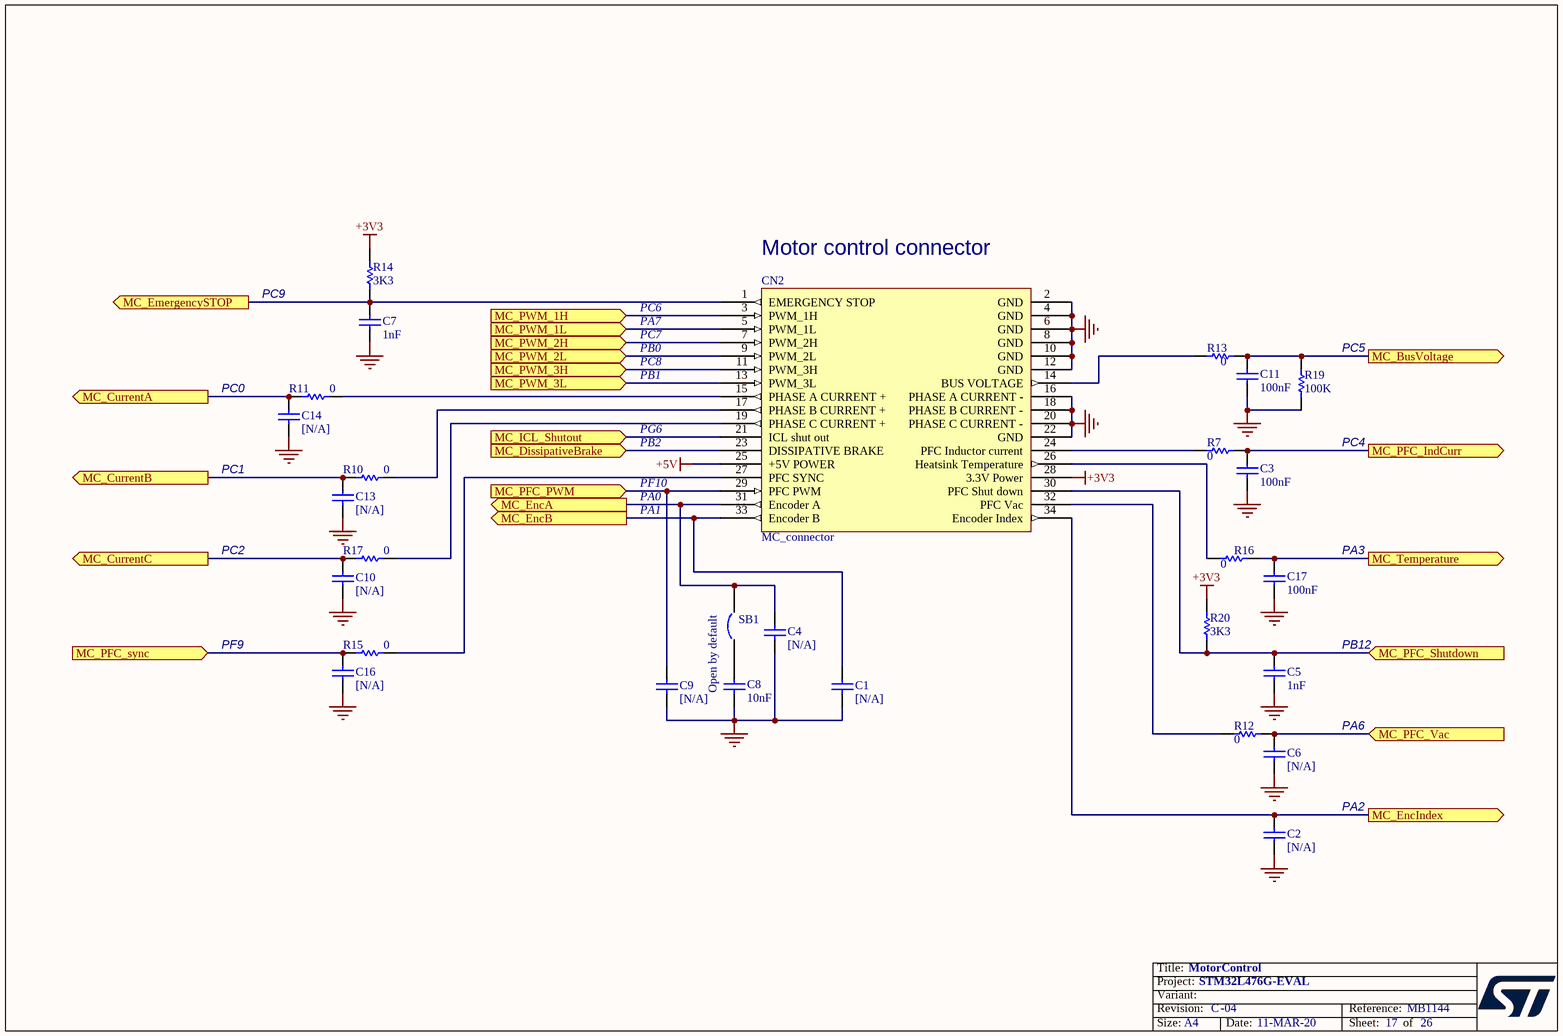
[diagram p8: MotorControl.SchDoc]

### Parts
C1  [N/A]  [0603C]
C2  [N/A]  [0603C]
C3  100nF  [0402C]
C4  [N/A]  [0603C]
C5  1nF  [0402C]
C6  [N/A]  [0603C]
C7  1nF  [0402C]
C8  10nF  [0402C]
C9  [N/A]  [0603C]
C10  [N/A]  [0603C]
C11  100nF  [0402C]
C13  [N/A]  [0603C]
C14  [N/A]  [0603C]
C16  [N/A]  [0603C]
C17  100nF  [0402C]
CN2  MC_connector  [IDC34S]
R7  0  [0603R]
R10  0  [0603R]
R11  0  [0603R]
R12  0  [0603R]
R13  0  [0603R]
R14  3K3  [0402R]
R15  0  [0603R]
R16  0  [0603R]
R17  0  [0603R]
R19  100K  [0402R]
R20  3K3  [0402R]
SB1  Open by default  [SB_0603]

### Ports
MC_BusVoltage (out), MC_CurrentA (out), MC_CurrentB (out), MC_CurrentC (out), MC_DissipativeBrake (in), MC_EmergencySTOP (out), MC_EncA (out), MC_EncB (out), MC_EncIndex (out), MC_ICL_Shutout (in), MC_PFC_IndCurr (out), MC_PFC_PWM (in), MC_PFC_Shutdown (in), MC_PFC_sync (in), MC_PFC_Vac (in), MC_PWM_1H (in), MC_PWM_1L (in), MC_PWM_2H (in), MC_PWM_2L (in), MC_PWM_3H (in), MC_PWM_3L (in), MC_Temperature (out)

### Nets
+3V3: CN2.28(3.3V_Power) R14.2 R20.2
+5V: CN2.25(+5V_POWER)
GND: C1.1 C2.1 C3.2 C4.1 C5.1 C6.1 C7.1 C8.2 C9.1 C10.1 C11.2 C13.1 C14.1 C16.1 C17.2 CN2.2(GND) CN2.4(GND) CN2.6(GND) CN2.8(GND) CN2.10(GND) CN2.12(GND) CN2.16(PHASE_A_CURRENT_-) CN2.18(PHASE_B_CURRENT_-) CN2.20(PHASE_C_CURRENT_-) CN2.22(GND) R19.2
NetC1_2: C1.2 CN2.33(Encoder_B) ; port MC_EncB
NetC2_2: C2.2 CN2.34(Encoder_Index) ; port MC_EncIndex
NetC3_1: C3.1 R7.2 ; port MC_PFC_IndCurr
NetC4_2: C4.2 CN2.31(Encoder_A) SB1.2 ; port MC_EncA
NetC5_2: C5.2 CN2.30(PFC_Shut_down) R20.1 ; port MC_PFC_Shutdown
NetC6_2: C6.2 R12.2 ; port MC_PFC_Vac
NetC7_2: C7.2 CN2.1(EMERGENCY_STOP) R14.1 ; port MC_EmergencySTOP
NetC8_1: C8.1 SB1.1
NetC9_2: C9.2 CN2.29(PFC_PWM) ; port MC_PFC_PWM
NetC10_2: C10.2 R17.1 ; port MC_CurrentC
NetC11_1: C11.1 R13.2 R19.1 ; port MC_BusVoltage
NetC13_2: C13.2 R10.1 ; port MC_CurrentB
NetC14_2: C14.2 R11.1 ; port MC_CurrentA
NetC16_2: C16.2 R15.1 ; port MC_PFC_sync
NetC17_1: C17.1 R16.2 ; port MC_Temperature
NetCN2_3: CN2.3(PWM_1H) ; port MC_PWM_1H
NetCN2_5: CN2.5(PWM_1L) ; port MC_PWM_1L
NetCN2_7: CN2.7(PWM_2H) ; port MC_PWM_2H
NetCN2_9: CN2.9(PWM_2L) ; port MC_PWM_2L
NetCN2_11: CN2.11(PWM_3H) ; port MC_PWM_3H
NetCN2_13: CN2.13(PWM_3L) ; port MC_PWM_3L
NetCN2_14: CN2.14(BUS_VOLTAGE) R13.1
NetCN2_15: CN2.15(PHASE_A_CURRENT_+) R11.2
NetCN2_17: CN2.17(PHASE_B_CURRENT_+) R10.2
NetCN2_19: CN2.19(PHASE_C_CURRENT_+) R17.2
NetCN2_21: CN2.21(ICL_shut_out) ; port MC_ICL_Shutout
NetCN2_23: CN2.23(DISSIPATIVE_BRAKE) ; port MC_DissipativeBrake
NetCN2_24: CN2.24(PFC_Inductor_current) R7.1
NetCN2_26: CN2.26(Heatsink_Temperature) R16.1
NetCN2_27: CN2.27(PFC_SYNC) R15.2
NetCN2_32: CN2.32(PFC_Vac) R12.1

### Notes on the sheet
- PC9
- PC6
- (near CN2) Motor control connector
- PA7
- PB0
- PB1
- PC7
- PC8
- (near R19) PC5
- PC0
- PG6
- PB2
- PC4
- PC1
- PA1
- PA0
- PF10
- PC2
- PA3
- PF9
- PB12
- PA6
- PA2

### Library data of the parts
C1 C2 C4 C6 C9 C10 C13 C14 C16 = cap: Capacitor; Value: 100pF; Ordered by: Subcon; ECCN_US/EU: NA; Fitted: NO
C3 C11 C17 = Cap: as C132 on sheet IO_Expandor
C5 C7 C8 = CAP: as C141 on sheet MCU2
CN2 = MC_connector_1: Ordered by: Subcon; Comments: Motor Control conn.; ECCN_US/EU: NA
R7 R10-R17 R20 = Res1: as R108 on sheet LCD_Glass
R19 = res1: as R107 on sheet LCD_Glass
SB1 = Circuit Breaker: as SB2 on sheet MCU2

## Sheet MicroSD.SchDoc: MicroSD
size A4; DocumentNumber: 12; Revision: C-02; SheetNumber: 12; SheetTotal: 26; Project: STM32L476G-EVAL
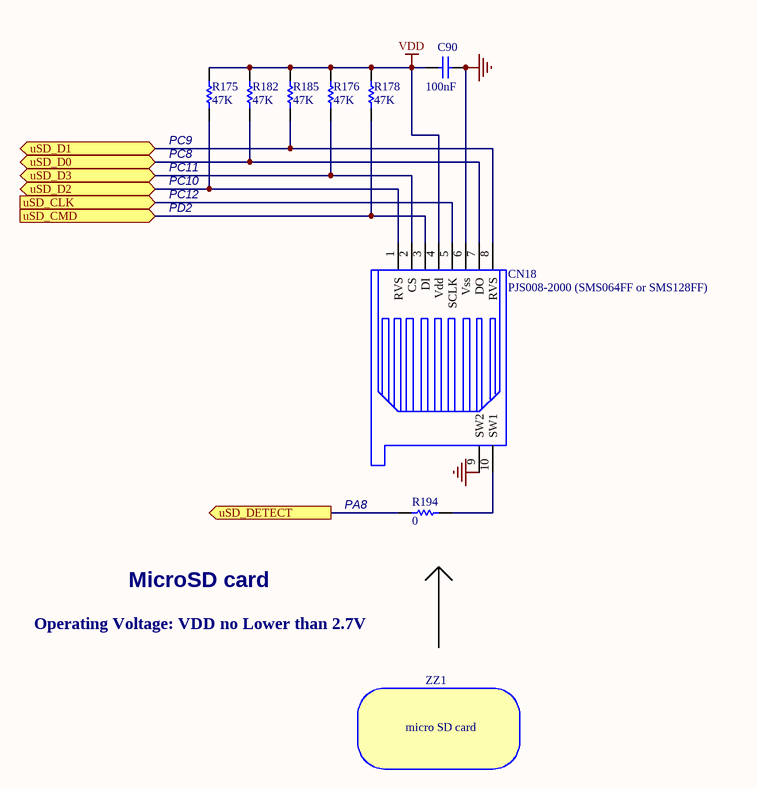
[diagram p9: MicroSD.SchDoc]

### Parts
C90  100nF  [0402C]
CN18  PJS008-2000 (SMS064FF or SMS128FF)  [MSD_PJS008_]
R175  47K  [0402R]
R176  47K  [0402R]
R178  47K  [0402R]
R182  47K  [0402R]
R185  47K  [0402R]
R194  0  [0603R]
ZZ1  micro SD card

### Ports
uSD_CLK (in), uSD_CMD (in), uSD_D0 (bidir), uSD_D1 (bidir), uSD_D2 (bidir), uSD_D3 (bidir), uSD_DETECT (out)

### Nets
GND: C90.2 CN18.6(Vss) CN18.9(SW2)
VDD: C90.1 CN18.4(Vdd) R175.1 R176.1 R178.1 R182.1 R185.1
NetCN11_4: R194.1 ; port uSD_DETECT
NetCN14_2: CN18.3(DI) R178.2 ; port uSD_CMD
NetCN18_1: CN18.1(RVS) R175.2 ; port uSD_D2
NetCN18_2: CN18.2(CS) R176.2 ; port uSD_D3
NetCN18_5: CN18.5(SCLK) ; port uSD_CLK
NetCN18_7: CN18.7(DO) R182.2 ; port uSD_D0
NetCN18_8: CN18.8(RVS) R185.2 ; port uSD_D1
NetCN18_10: CN18.10(SW1) R194.2

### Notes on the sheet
- (near R175) PC9
- (near R175) PC8
- PC10
- PC11
- PC12
- PD2
- PA8
- MicroSD card
- Operating Voltage: VDD no Lower than 2.7V

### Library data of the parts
C90 = CAP: as C141 on sheet MCU2
CN18 = SMS016AFA5E: ECCN_US/EU: NA; Ordered by: Subcon; Assembly: with SD card; Comments: Micro SD card connector
R175 R176 R178 R182 R185 R194 = Res1: as R108 on sheet LCD_Glass
ZZ1 = BoM_Item: 4GB or more; Ordered by: Subcon; Assembly: to plug in CN18

## Sheet QSPI.SchDoc: QSPI
size A4; DocumentNumber: 14; Revision: C-02; SheetNumber: 14; SheetTotal: 26; Project: STM32L476G-EVAL
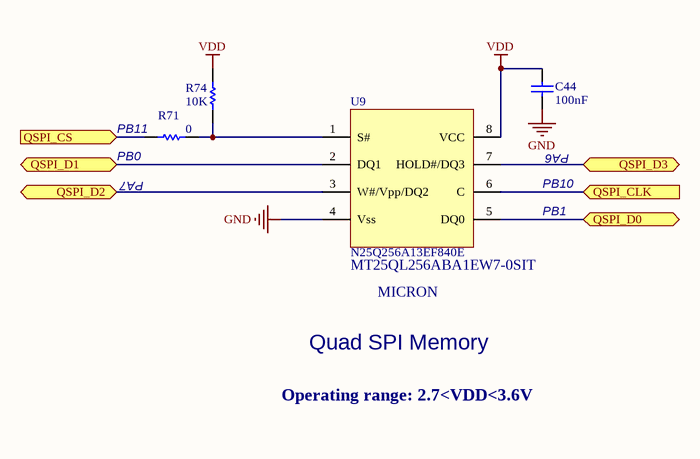
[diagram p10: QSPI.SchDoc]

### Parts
C44  100nF  [0402C]
R71  0  [0603R]
R74  10K  [0402R]
U9  MT25QL256ABA1EW7-0SIT  [ICC_W-PDFN-8_8X6_P127]

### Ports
QSPI_CLK (in), QSPI_CS (in), QSPI_D0 (bidir), QSPI_D1 (bidir), QSPI_D2 (bidir), QSPI_D3 (bidir)

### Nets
GND: C44.2 U9.4(Vss)
VDD: C44.1 R74.1 U9.8(VCC)
NetR71_1: R71.1 R74.2 U9.1(S#)
NetR71_2: R71.2 ; port QSPI_CS
NetSB9_1: U9.6(C) ; port QSPI_CLK
NetSB12_1: U9.5(DQ0) ; port QSPI_D0
NetSB14_1: U9.2(DQ1) ; port QSPI_D1
NetSB18_1: U9.3(W#/Vpp/DQ2) ; port QSPI_D2
NetSB21_1: U9.7(HOLD#/DQ3) ; port QSPI_D3

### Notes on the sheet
- (near R71) PB0
- (near R71) PB11
- PA6
- (near R71) PA7
- PB1
- PB10
- (near U9) N25Q256A13EF840E
- MICRON
- Quad SPI Memory
- Operating range: 2.7<VDD<3.6V

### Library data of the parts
C44 = Cap: as C132 on sheet IO_Expandor
R71 = Res1: as R108 on sheet LCD_Glass
R74 = res1: as R107 on sheet LCD_Glass
U9 = MCD-02467: Memory, Serial NOR Flash Memory, 256Mb, 3V; Part_Type: IC; Part_Preference: Recommended; Manufacturer: MICRON; Manufacturer_Part_Number: MT25QL256ABA1EW9-0SIT

## Sheet Extension connector.SCHDOC: Extension connector
size A4; DocumentNumber: 24; Revision: C-02; SheetNumber: 24; SheetTotal: 26; Project: STM32L476G-EVAL
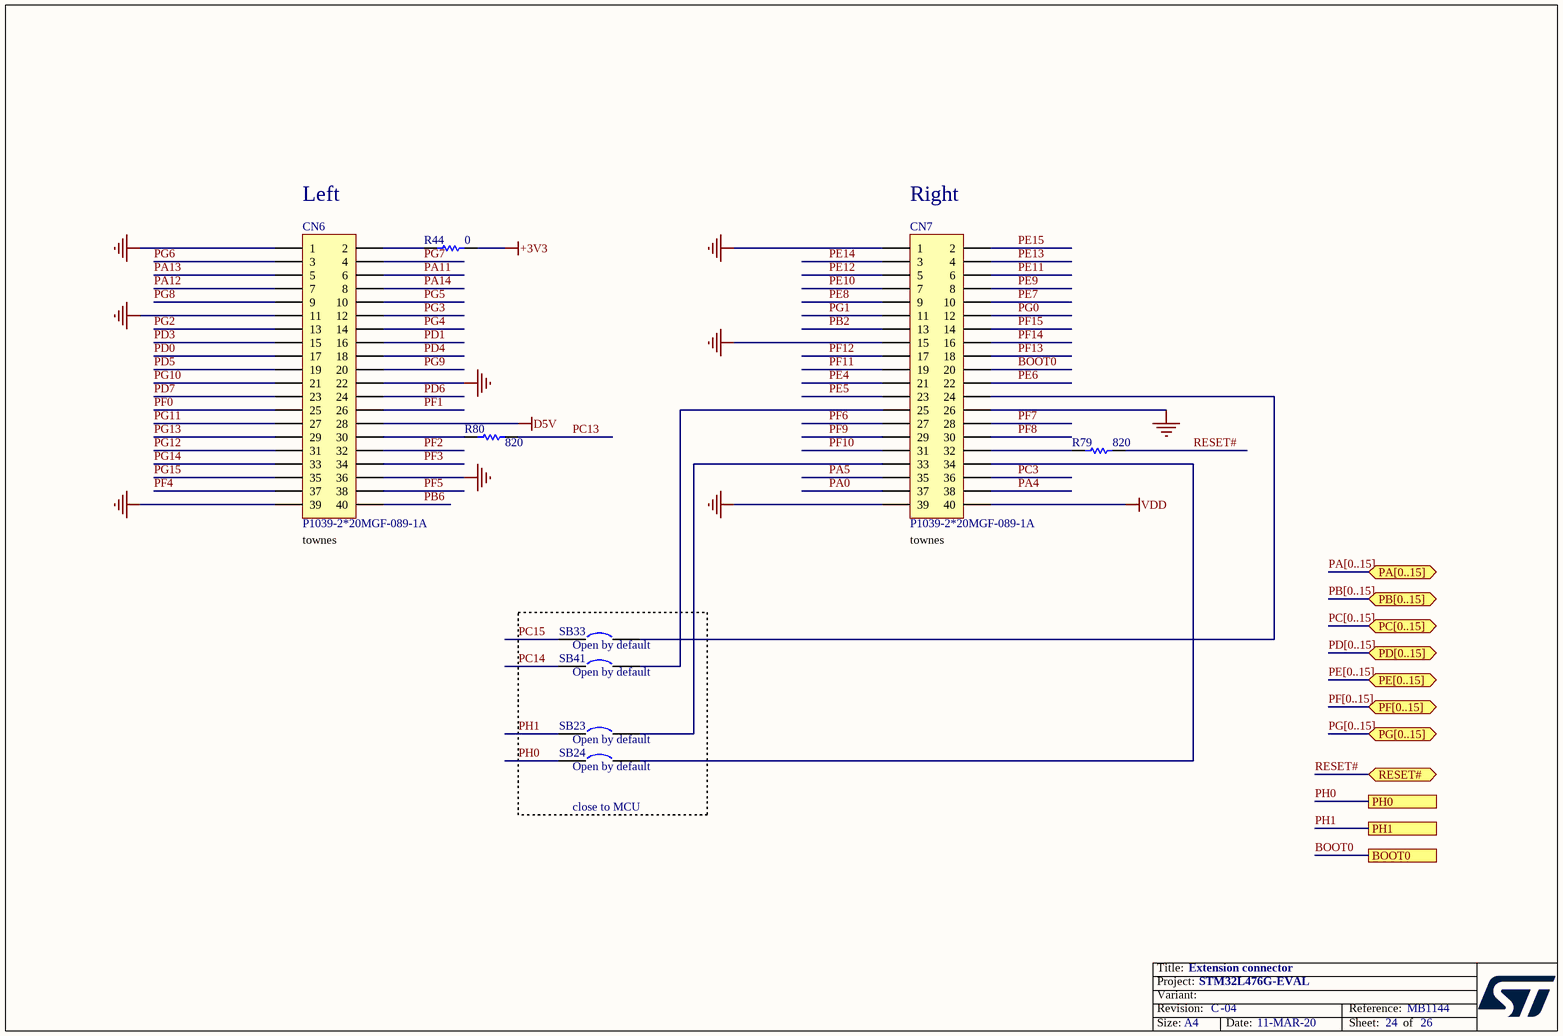
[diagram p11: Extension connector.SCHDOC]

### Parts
CN6  P1039-2*20MGF-089-1A  [FTR-120-53-L-D-LC]
CN7  P1039-2*20MGF-089-1A  [FTR-120-53-L-D-LC]
R44  0  [0603R]
R79  820  [0402R]
R80  820  [0402R]
SB23  Open by default  [SB_0603]
SB24  Open by default  [SB_0603]
SB33  Open by default  [SB_0603]
SB41  Open by default  [SB_0603]

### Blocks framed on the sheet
close to MCU: SB23 SB24 SB33 SB41

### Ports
BOOT0, PA[0..15] (bidir), PB[0..15] (bidir), PC[0..15] (bidir), PD[0..15] (bidir), PE[0..15] (bidir), PF[0..15] (bidir), PG[0..15] (bidir), PH0, PH1, RESET# (bidir)

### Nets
+3V3: R44.1
D5V: CN6.28
GND: CN6.1 CN6.11 CN6.22 CN6.36 CN6.39 CN7.1 CN7.15 CN7.26 CN7.39
VDD: CN7.40
BOOT0: CN7.20 ; port BOOT0
PA0: CN7.37
PA4: CN7.38
PA5: CN7.35
PA11: CN6.6
PA12: CN6.7
PA13: CN6.5
PA14: CN6.8
PB2: CN7.13
PB6: CN6.40
PC3: CN7.36
PC13: R80.2
PC14: SB41.1
PC15: SB33.1
PD0: CN6.17  [project net D2]
PD1: CN6.16  [project net D3]
PD3: CN6.15
PD4: CN6.18
PD5: CN6.19
PD6: CN6.24
PD7: CN6.23
PE4: CN7.21
PE5: CN7.23
PE6: CN7.22
PE7: CN7.10  [project net D4]
PE8: CN7.9  [project net D5]
PE9: CN7.8  [project net D6]
PE10: CN7.7  [project net D7]
PE11: CN7.6  [project net D8]
PE12: CN7.5  [project net D9]
PE13: CN7.4  [project net D10]
PE14: CN7.3  [project net D11]
PE15: CN7.2  [project net D12]
PF0: CN6.25  [project net A0]
PF1: CN6.26  [project net A1]
PF2: CN6.32  [project net A2]
PF3: CN6.34  [project net A3]
PF4: CN6.37  [project net A4]
PF5: CN6.38  [project net A5]
PF6: CN7.27
PF7: CN7.28
PF8: CN7.30
PF9: CN7.29
PF10: CN7.31
PF11: CN7.19
PF12: CN7.17  [project net A6]
PF13: CN7.18  [project net A7]
PF14: CN7.16  [project net A8]
PF15: CN7.14  [project net A9]
PG0: CN7.12  [project net A10]
PG1: CN7.11  [project net A11]
PG2: CN6.13  [project net A12]
PG3: CN6.12  [project net A13]
PG4: CN6.14  [project net A14]
PG5: CN6.10  [project net A15]
PG6: CN6.3
PG7: CN6.4
PG8: CN6.9
PG9: CN6.20
PG10: CN6.21  [project net LCD_NE3]
PG11: CN6.27
PG12: CN6.31
PG13: CN6.29
PG14: CN6.33
PG15: CN6.35
PH0: SB24.1 ; port PH0
PH1: SB23.1 ; port PH1
RESET#: R79.1 ; port RESET#
NetCN6_2: CN6.2 R44.2
NetCN6_30: CN6.30 R80.1
NetCN7_24: CN7.24 SB33.2
NetCN7_25: CN7.25 SB41.2
NetCN7_32: CN7.32 R79.2
NetCN7_33: CN7.33 SB23.2
NetCN7_34: CN7.34 SB24.2

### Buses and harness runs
bus PA[0..15] = port PA[0..15]
bus PB[0..15] = port PB[0..15]
bus PC[0..15] = port PC[0..15]
bus PD[0..15] = port PD[0..15]
bus PE[0..15] = port PE[0..15]
bus PF[0..15] = port PF[0..15]
bus PG[0..15] = port PG[0..15]

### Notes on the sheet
- (near CN6) Left
- (near CN7) Right
- (near CN6) townes
- (near CN7) townes

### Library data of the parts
CN6 CN7 = FTR-120-53-L-D-LC: Header, 20-Pin, Dual row; Ordered by: Subcon; Comments: extension connector; ECCN_US/EU: NA
R44 R79 R80 = Res1: as R108 on sheet LCD_Glass
SB23 SB24 SB33 SB41 = Circuit Breaker: as SB2 on sheet MCU2

## Sheet JTAG&Trace.SchDoc: JTAG&Trace
size A4; DocumentNumber: 10; Revision: C-02; SheetNumber: 10; SheetTotal: 26; Project: STM32L476G-EVAL
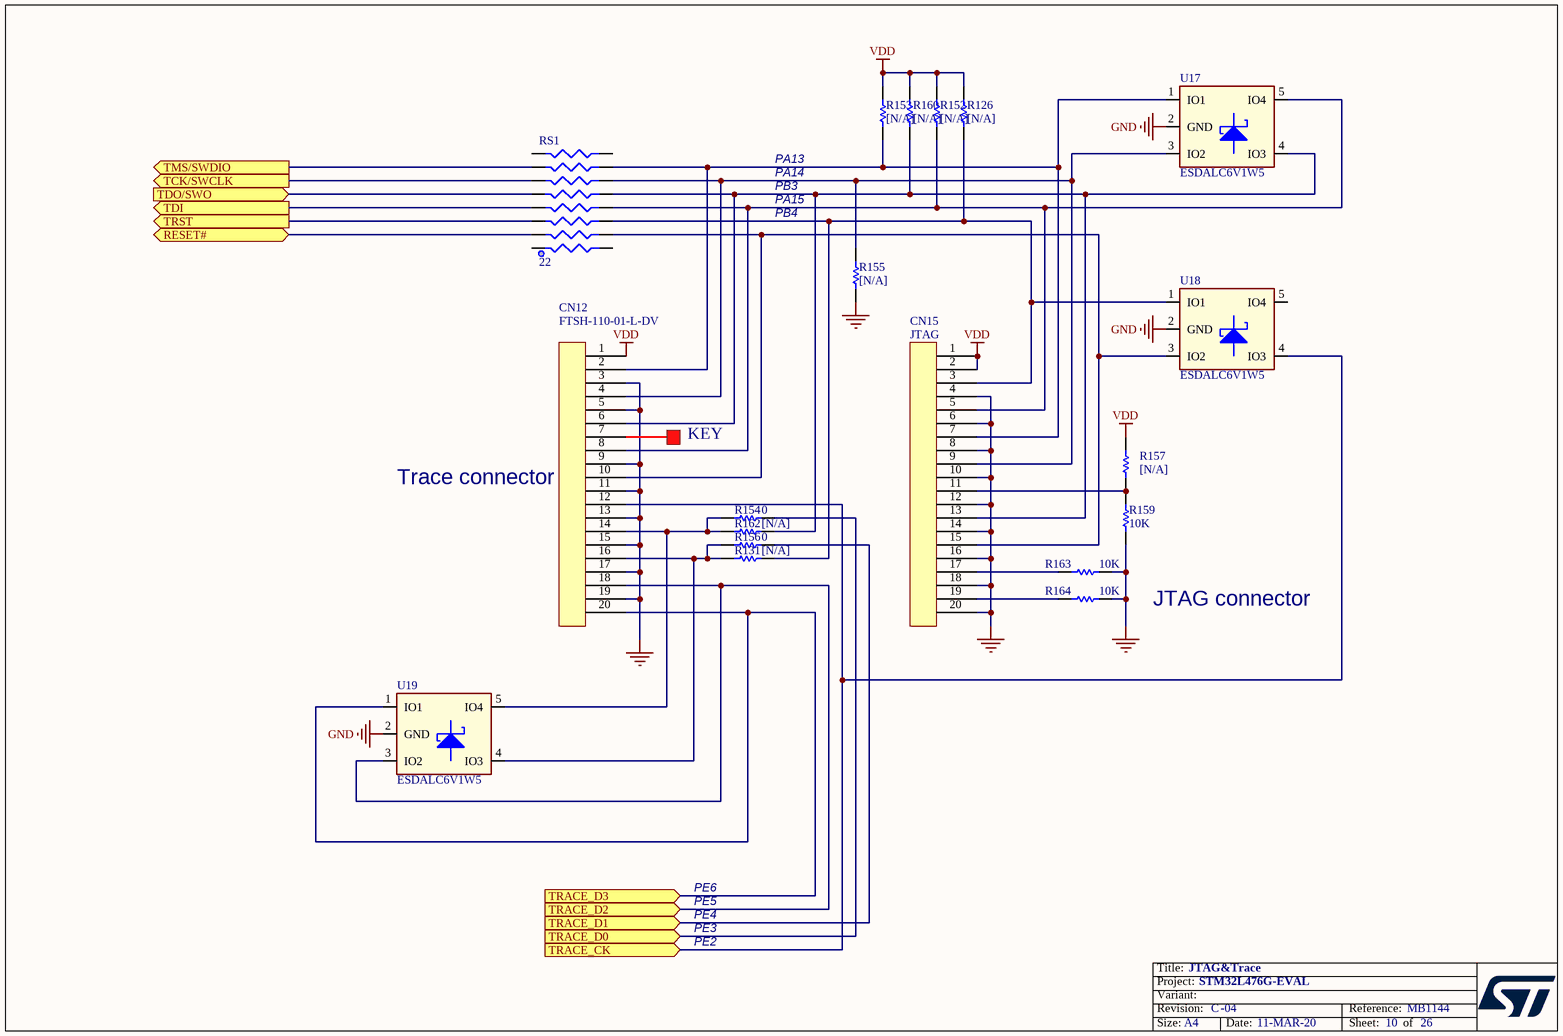
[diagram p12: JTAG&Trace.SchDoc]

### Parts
CN12  FTSH-110-01-L-DV  [FTSH-110-01-L-DV]
CN15  JTAG  [IDC20S]
R126  [N/A]  [0603R]
R131  [N/A]  [0603R]
R152  [N/A]  [0603R]
R153  [N/A]  [0603R]
R154  0  [0603R]
R155  [N/A]  [0603R]
R156  0  [0603R]
R157  [N/A]  [0603R]
R159  10K  [0402R]
R160  [N/A]  [0603R]
R162  [N/A]  [0603R]
R163  10K  [0402R]
R164  10K  [0402R]
RS1  22  [RP0402X8_REV]
U17  ESDALC6V1W5  [SOT-353]
U18  ESDALC6V1W5  [SOT-353]
U19  ESDALC6V1W5  [SOT-353]

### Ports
RESET# (bidir), TCK/SWCLK (out), TDI (out), TDO/SWO (in), TMS/SWDIO (out), TRACE_CK (in), TRACE_D0 (in), TRACE_D1 (in), TRACE_D2 (in), TRACE_D3 (in), TRST (out)

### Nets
GND: CN12.3 CN12.5 CN12.9 CN12.11 CN12.13 CN12.15 CN12.17 CN12.19 CN15.4 CN15.6 CN15.8 CN15.10 CN15.12 CN15.14 CN15.16 CN15.18 CN15.20 R155.1 R159.1 R163.1 R164.1 U17.2(GND) U18.2(GND) U19.2(GND)
VDD: CN12.1 CN15.1 CN15.2 R126.2 R152.2 R153.2 R157.2 R160.2
LCDSEG7: RS1.9 ; port TDO/SWO
LCDSEG8: RS1.5 ; port TRST
LCDSEG17: RS1.7 ; port TDI
PA13: RS1.13 ; port TMS/SWDIO
PA14: RS1.11 ; port TCK/SWCLK
RESET#: RS1.3 ; port RESET#
NetCN12_2: CN12.2 CN15.7 R153.1 RS1.14 U17.1(IO1)
NetCN12_4: CN12.4 CN15.9 R155.2 RS1.12 U17.3(IO2)
NetCN12_6: CN12.6 CN15.13 R160.1 R162.2 RS1.10 U17.4(IO3)
NetCN12_8: CN12.8 CN15.5 R152.1 RS1.8 U17.5(IO4)
NetCN12_10: CN12.10 CN15.15 RS1.4 U18.3(IO2)
NetCN12_12: CN12.12 U18.4(IO3) ; port TRACE_CK
NetCN12_14: CN12.14 R154.1 R162.1 U19.5(IO4)
NetCN12_16: CN12.16 R131.1 R156.1 U19.4(IO3)
NetCN12_18: CN12.18 U19.3(IO2) ; port TRACE_D2
NetCN12_20: CN12.20 U19.1(IO1) ; port TRACE_D3
NetCN15_3: CN15.3 R126.1 R131.2 RS1.6 U18.1(IO1)
NetCN15_11: CN15.11 R157.1 R159.2
NetCN15_17: CN15.17 R163.2
NetCN15_19: CN15.19 R164.2
NetR104_1: R154.2 ; port TRACE_D0
NetR156_2: R156.2 ; port TRACE_D1

Not connected (* = marked no-connect by the designer): CN12 7; RS1 1 2 15 16; U18 5(IO4)

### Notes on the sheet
- PA13
- PA14
- PB3
- PA15
- PB4
- KEY
- (near CN12) Trace connector
- JTAG connector
- PE6
- PE5
- PE4
- PE3
- PE2

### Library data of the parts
CN12 = 20PIN1: Ordered by: Subcon; Comments: Trace connector; Assembly: with pin7 removed; ECCN_US/EU: NA
CN15 = 20PIN1: Ordered by: Subcon; Comments: JTAG connector; ECCN_US/EU: NA
R126 R131 R152 R153 R155 R157 R160 R162 = Res1: as R231 on sheet IO_Expandor
R154 R156 R159 R163 R164 = Res1: as R108 on sheet LCD_Glass
RS1 = RES8B: Ordered by: Subcon; ECCN_US/EU: NA
U17-U19 = ESDALC6V1W5: Dual Transil array for ESD protection; Manuf_1: ST; Ref St: 9151112; Order: ESDA5V3L; ECCN_US/EU: EAR99/NEC

## Sheet ST_LINK.SCHDOC: ST_LINK
size A4; DocumentNumber: 9; Revision: C-02; SheetNumber: 9; SheetTotal: 26; Project: STM32L476G-EVAL
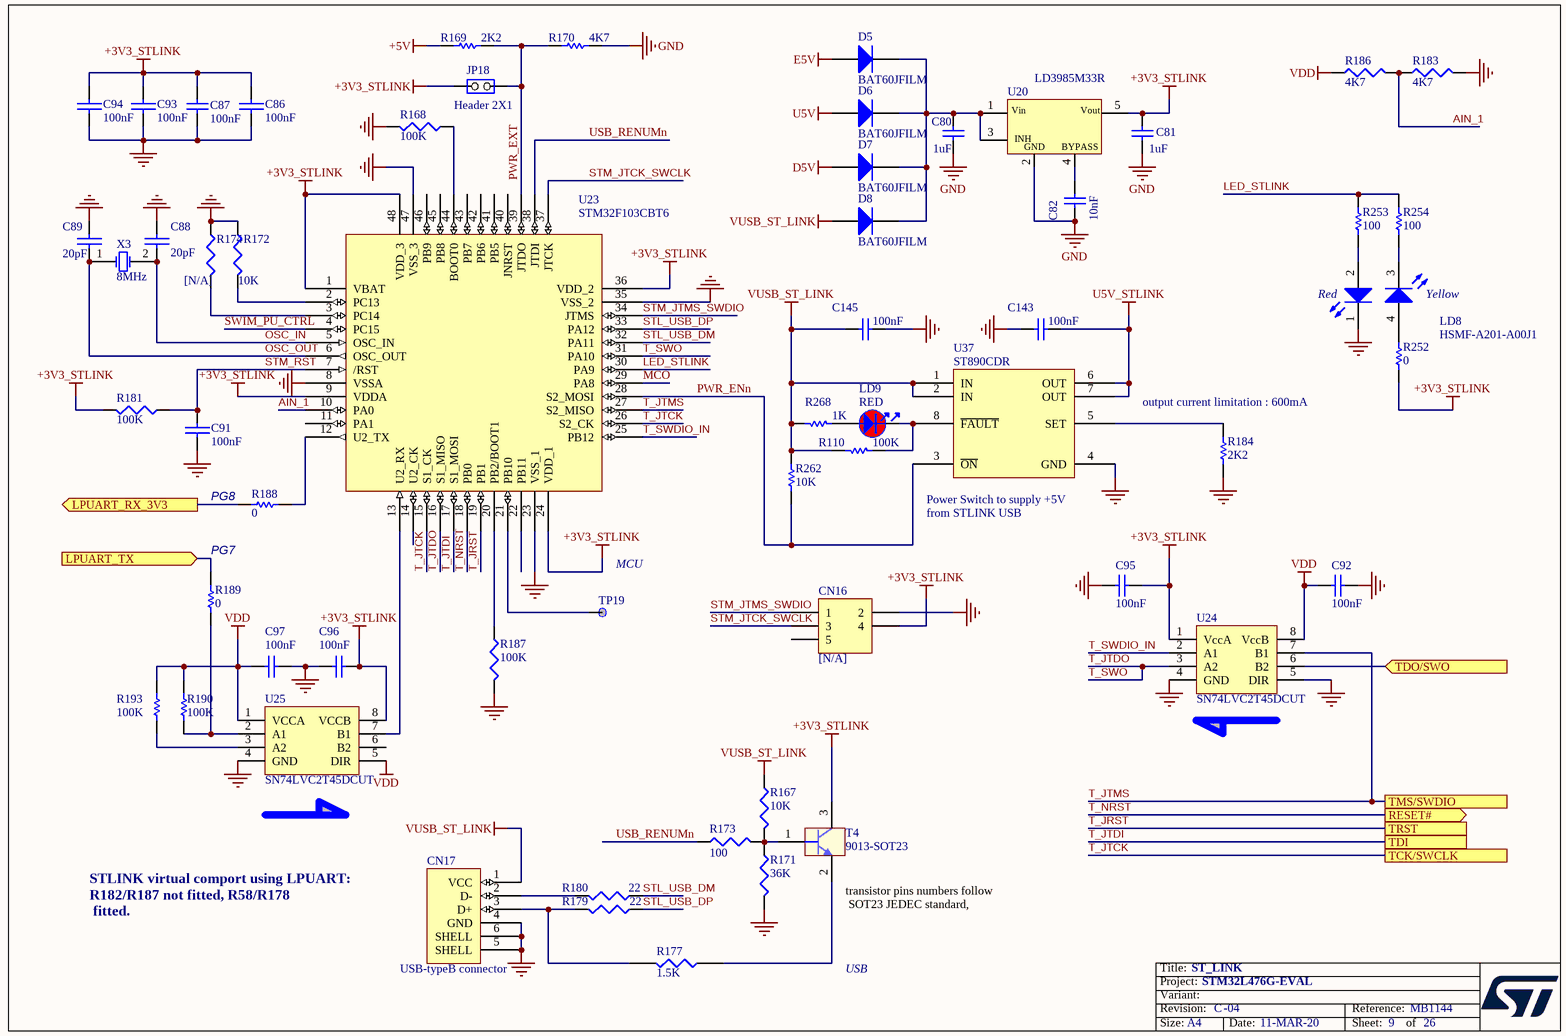
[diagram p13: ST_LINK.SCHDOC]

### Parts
C80  1uF  [0603C]
C81  1uF  [0603C]
C82  10nF  [0402C]
C86  100nF  [0402C]
C87  100nF  [0402C]
C88  20pF  [0402R]
C89  20pF  [0402R]
C91  100nF  [0402C]
C92  100nF  [0402C]
C93  100nF  [0402C]
C94  100nF  [0402C]
C95  100nF  [0402C]
C96  100nF  [0402C]
C97  100nF  [0402C]
C143  100nF  [0402C]
C145  100nF  [0402C]
CN16  [N/A]  [HDR_2X3-1_2R54-6]
CN17  USB-typeB connector  [USB-B]
D5  BAT60JFILM  [SOD-323]
D6  BAT60JFILM  [SOD-323]
D7  BAT60JFILM  [SOD-323]
D8  BAT60JFILM  [SOD-323]
JP18  Header 2X1  [SIP2]
LD8  HSMF-A201-A00J1  [LED2_3528]
LD9  value RED  [LED_0603_RED_H0P4]  (hidden comment: LED_red)
R110  100K  [0402R]
R167  10K  [0402R]
R168  100K  [0402R]
R169  2K2  [0402R]
R170  4K7  [0402R]
R171  36K  [0402R]
R172  10K  [0402R]
R173  100  [0402R]
R174  [N/A]  [0603R]
R177  1.5K  [0402R]
R179  22  [0402R]
R180  22  [0402R]
R181  100K  [0402R]
R183  4K7  [0402R]
R184  2K2  [0402R]
R186  4K7  [0402R]
R187  100K  [0402R]
R188  0  [0603R]
R189  0  [0603R]
R190  100K  [0402R]
R193  100K  [0402R]
R252  0  [0603R]
R253  100  [0402R]
R254  100  [0402R]
R262  10K  [0402R]
R268  1K  [0402R]
T4  9013-SOT23  [SOT-23]
TP19  [N/A]  [TP_C79]  (value not drawn)
U20  LD3985M33R  [SOT23-5]
U23  STM32F103CBT6  [LQFP48_0R5_9X9]
U24  SN74LVC2T45DCUT  [USOP8_0R5_2X3R1]
U25  SN74LVC2T45DCUT  [USOP8_0R5_2X3R1]
U37  ST890CDR  [SOIC8_1R27_4R9X6]
X3  8MHz  [XTAL_2SM_12R7X4R7]

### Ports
LPUART_RX_3V3 (out), LPUART_TX (in), RESET# (out), TCK/SWCLK, TDI, TDO/SWO (in), TMS/SWDIO, TRST

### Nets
+3V3_STLINK: C81.1 C86.2 C87.1 C93.2 C94.2 C95.2 C96.1 CN16.4 JP18.1(COMMON) R181.2 R252.2 T4.3(C) U20.5(Vout) U23.1(VBAT) U23.9(VDDA) U23.24(VDD_1) U23.36(VDD_2) U23.48(VDD_3) U24.1(VccA) U25.8(VCCB)
+5V: R169.2
D5V: D7.1(A)
E5V: D5.1(A)
GND: C80.2 C81.2 C82.2 C86.1 C87.2 C88.1 C89.1 C91.1 C92.2 C93.1 C94.1 C95.1 C96.2 C97.2 C143.1 C145.2 CN16.2 CN17.4(GND) CN17.5(SHELL) CN17.6(SHELL) LD8.1(RED_cathode) R168.2 R170.1 R171.2 R172.1 R174.1 R183.2 R184.2 R187.2 U20.2(GND) U23.8(VSSA) U23.23(VSS_1) U23.35(VSS_2) U23.47(VSS_3) U24.4(GND) U24.5(DIR) U25.4(GND) U37.4(GND)
U5V: D6.1(A)
U5V_STLINK: C143.2 U37.6(OUT) U37.7(OUT)
VDD: C92.1 C97.1 R186.1 R190.1 R193.1 U24.8(VccB) U25.1(VCCA) U25.5(DIR)
VUSB_ST_LINK: C145.1 CN17.1(VCC) D8.1(A) R110.1 R167.1 R262.2 R268.1 U37.1(IN) U37.2(IN)
AIN_1: R183.1 R186.2 U23.10(PA0)
LCDSEG7: U24.6(B2) ; port TDO/SWO
LED_STLINK: R253.1 R254.1 U23.30(PA9)
MCO: U23.29(PA8)
OSC_IN: C88.2 U23.5(OSC_IN) X3.2(OSC2)
OSC_OUT: C89.2 U23.6(OSC_OUT) X3.1(OSC1)
PG8: R188.2 ; port LPUART_RX_3V3
PWR_ENn: R262.1 U23.28(S2_MOSI) U37.3(~{ON})
PWR_EXT: JP18.2(NO) R169.1 R170.2 U23.39(JTDO)
STL_USB_DM: R180.1 U23.32(PA11)
STL_USB_DP: R179.1 U23.33(PA12)
STM_JTCK_SWCLK: CN16.3 U23.37(JTCK)
STM_JTMS_SWDIO: CN16.1 U23.34(JTMS)
STM_RST: C91.2 R181.1 U23.7(/RST)
SWIM_PU_CTRL: U23.4(PC15)
T_JRST: U23.19(PB1) ; port TRST  [project net LCDSEG8]
T_JTCK: U23.15(S1_CK) U23.26(S2_CK) ; port TCK/SWCLK  [project net PA14]
T_JTDI: U23.17(S1_MOSI) ; port TDI  [project net LCDSEG17]
T_JTDO: U23.16(S1_MISO) U23.31(PA10) U24.3(A2)  [also labelled T_SWO]
T_JTMS: U23.27(S2_MISO) U24.7(B1) ; port TMS/SWDIO  [project net PA13]
T_NRST: U23.18(PB0) ; port RESET#  [project net RESET#]
T_SWDIO_IN: U23.25(PB12) U24.2(A1)
USB_RENUMn: R173.1 U23.38(JTDI)
NetC80_1: C80.1 D5.2(K) D6.2(K) D7.2(K) D8.2(K) U20.1(Vin) U20.3(CE)
NetC82_1: C82.1 U20.4(BYPASS)
NetCN17_2: CN17.2(D-) R180.2
NetCN17_3: CN17.3(D+) R177.2 R179.2
NetLD8_2: LD8.2(Red_anode) R253.2
NetLD8_3: LD8.3(YellowGreen_cathode) R254.2
NetLD8_4: LD8.4(YellowGreen_anode) R252.1
NetLD9_1: LD9.1 R268.2
NetLD9_2: LD9.2 R110.2 U37.8(~{FAULT})
NetR34_1: R189.1 ; port LPUART_TX
NetR167_2: R167.2 R171.1 R173.2 T4.1(B)
NetR168_1: R168.1 U23.44(BOOT0)
NetR172_2: R172.2 U23.2(PC13)
NetR174_2: R174.2 U23.3(PC14)
NetR177_1: R177.1 T4.2(E)
NetR184_1: R184.1 U37.5(SET)
NetR187_1: R187.1 U23.20(PB2/BOOT1)
NetR188_1: R188.1 U23.12(U2_TX)
NetR189_2: R189.2 R190.2 U25.2(A1)
NetR193_2: R193.2 U25.3(A2)
NetTP19_1: TP19.1 U23.21(PB10)
NetU23_13: U23.13(U2_RX) U25.7(B1)

Not connected (* = marked no-connect by the designer): CN16 5; U23 11(PA1) 14(U2_CK) 22(PB11) 40(JNRST) 41(PB5) 42(PB6) 43(PB7) 45(PB8) 46(PB9); U25 6(B2)

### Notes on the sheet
- (near R184) output current limitation : 600mA
- (near R188) PG8
- (near R189) PG7
- (near TP19) MCU
- (near U37) Power Switch to supply +5V from STLINK USB
- STLINK virtual comport using LPUART: R182/R187 not fitted, R58/R178
  fitted.
- (near T4) transistor pins numbers follow
  SOT23 JEDEC standard,
- USB

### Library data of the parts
C80 C81 = CAP: as C58 on sheet MCU2
C82 = Cap: Capacitor; Ordered by: Subcon; ECCN_US/EU: NA
C86 C91 C93 C94 = CAP: Ordered by: Subcon; ECCN_US/EU: NA
C87 = Cap: as C132 on sheet IO_Expandor
C88 C89 = CAP: as C134 on sheet IO_Expandor
C92 C95-C97 = CAP: as C141 on sheet MCU2
C143 C145 = Capacitor_ST: Capacitor 0402 / 0603 / 0805; Ordered by: Subcon; ECCN_US/EU: NA
CN16 = Header 3X2: Header, 3-Pin, Dual row; ECCN_US/EU: NA; Ordered by: Subcon; Comments: ST-LINK programming; Fitted: NO
CN17 = USB-typeB connector: ECCN_US/EU: NA; Ordered by: Subcon; Comments: ST-LINK/V2-1 connector
D5-D8 = Diode: as D3 on sheet MCU2
JP18 = JP2: Ordered by: Subcon; ECCN_US/EU: NA
LD8 = HSMF-A201-A00J1: Ordered by: Subcon; ECCN_US/EU: NA
LD9 = MCD-02787: LED, Red, VF : Min=1.7V , Max=2.2V, IF : 25mA, 0603 SMD; Part_Type: Display; Part_Preference: Alternate; Manufacturer: EVERLIGHT; Manufacturer_Part_Number: 19-217/R6C-AL1M2VY/6T; Partial_Alternate_Internal_Part_Number: MCD-02401; Component_Country_Of_Origin: China; Alternate_EMS: A; ShowFields: YES; ID: 4899
R110 R188-R190 R193 R252-R254 = Res1: as R108 on sheet LCD_Glass
R167 R171-R173 = R: Resistor; Right: 20; Bottom: 30; Ordered by: Subcon; ECCN_US/EU: NA
R168 R179-R181 R187 = RES1: Resistor; Ordered by: Subcon; ECCN_US/EU: NA
R169 R170 R184 = res1: as R107 on sheet LCD_Glass
R174 = R: Right: 20; Bottom: 30; Ordered by: Subcon; ECCN_US/EU: NA; Fitted: NO
R177 R183 R186 = RES1: Ordered by: Subcon; ECCN_US/EU: NA
R262 = Resistor_ST: Resistor; Ordered by: Subcon; ECCN_US/EU: NA
R268 = Res1: Resistor; Ordered by: Subcon; ECCN_US/EU: NA
T4 = 9013-SOT23: NPN Bipolar Transistor; Manuf_1: Taitron; Manuf_Part_1: MMBT9013; Ordered by: Subcon; ECCN_US/EU: EAR99/NEC
TP19 = TP: as TP7 on sheet MCU2
U20 = LD3985M33R: Ultra low drop-low noise BiCMOS voltage, regulators low ESR capacitors compatible; Manuf_1: ST; Ref St: 9176161; ECCN_US/EU: EAR99/NEC
U23 = STM32F10x(48pin): Ordered by: ST; ECCN_US/EU: 3A991A2/NEC; Ref St: 9175111
U24 U25 = SN74LVC2T45DCUT: Manuf_1: TI; Ordered by: Subcon; ECCN_US/EU: EAR99/NEC
U37 = ST890CDR: Ordered by: ST; ECCN_US/EU: EAR99/NEC; Ref St: 9172002
X3 = XTAL: Crystal Oscillator; Manuf_1: jfvny; Manuf_Part_1: SSL8000012AFDHF0-SJ28; Ordered by: Subcon; ECCN_US/EU: NA

## Sheet USART_IrDA.SchDoc: USART_IrDA
size A4; DocumentNumber: 22; Revision: C-02; SheetNumber: 22; SheetTotal: 26; Project: STM32L476G-EVAL
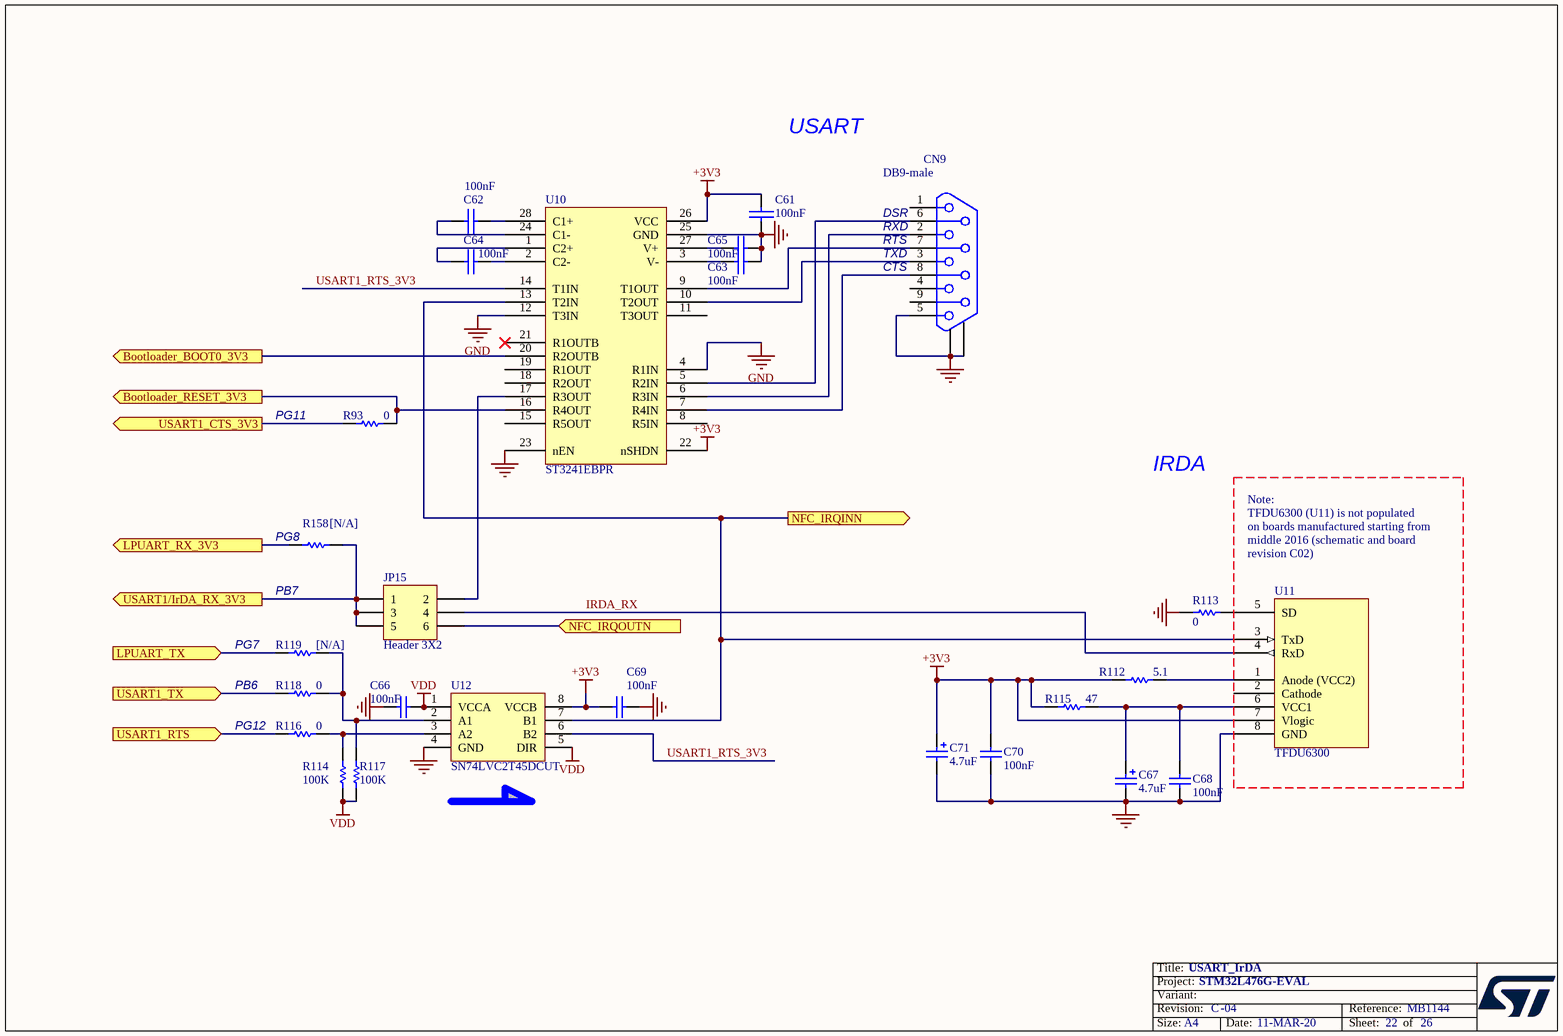
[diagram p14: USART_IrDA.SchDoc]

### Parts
C61  100nF  [0402C]
C62  100nF  [0402C]
C63  100nF  [0402C]
C64  100nF  [0402C]
C65  100nF  [0402C]
C66  100nF  [0402C]
C67  4.7uF  [TAN-A]
C68  100nF  [0402C]
C69  100nF  [0402C]
C70  100nF  [0402C]
C71  4.7uF  [TAN-A]
CN9  DB9-male  [DB9/M]
JP15  Header 3X2  [HDR_2X3_2R54]
R93  0  [0603R]
R112  5.1  [0402R]
R113  0  [0603R]
R114  100K  [0402R]
R115  47  [0402R]
R116  0  [0603R]
R117  100K  [0402R]
R118  0  [0603R]
R119  [N/A]  [0603R]
R158  [N/A]  [0603R]
U10  ST3241EBPR  [SSOP28_0R65_10R2X7R8]
U11  TFDU6300  [IR_VISHAY3]
U12  SN74LVC2T45DCUT  [USOP8_0R5_2X3R1]

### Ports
Bootloader_BOOT0_3V3 (out), Bootloader_RESET_3V3 (out), LPUART_RX_3V3 (out), LPUART_TX (in), NFC_IRQINN (out), NFC_IRQOUTN (in), USART1/IrDA_RX_3V3 (out), USART1_CTS_3V3 (out), USART1_RTS (in), USART1_TX (in)

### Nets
+3V3: C61.2 C69.2 C70.2 C71.1 R112.1 R115.1 U10.22(nSHDN) U10.26(VCC) U11.7(Vlogic) U12.8(VCCB)
GND: C61.1 C63.2 C65.2 C66.1 C67.2 C68.1 C69.1 C70.1 C71.2 CN9.5 CN9.10 CN9.11 R113.2 U10.4(R1IN) U10.12(T3IN) U10.23(nEN) U10.25(GND) U11.8(GND) U12.4(GND)
VDD: C66.2 R114.2 R117.2 U12.1(VCCA) U12.5(DIR)
IRDA_RX: JP15.4 U11.4(RxD)
PB6: R118.2 ; port USART1_TX
PG8: R158.2 ; port LPUART_RX_3V3
PG11: R93.2 ; port USART1_CTS_3V3
PG12: R116.2 ; port USART1_RTS
USART1_RTS_3V3: U10.14(T1IN) U12.6(B2)
NetC62_1: C62.1 U10.24(C1-)
NetC62_2: C62.2 U10.28(C1+)
NetC63_1: C63.1 U10.3(V-)
NetC64_1: C64.1 U10.1(C2+)
NetC64_2: C64.2 U10.2(C2-)
NetC65_1: C65.1 U10.27(V+)
NetC67_1: C67.1 C68.2 R115.2 U11.6(VCC1)
NetCN9_2: CN9.2 U10.6(R3IN)
NetCN9_3: CN9.3 U10.10(T2OUT)
NetCN9_6: CN9.6 U10.5(R2IN)
NetCN9_7: CN9.7 U10.9(T1OUT)
NetCN9_8: CN9.8 U10.7(R4IN)
NetCN13_1: JP15.6 ; port NFC_IRQOUTN
NetCN13_2: U10.13(T2IN) U11.3(TxD) U12.7(B1) ; port NFC_IRQINN
NetCN14_10: JP15.1 JP15.3 JP15.5 R158.1 ; port USART1/IrDA_RX_3V3
NetD4_2: R93.1 U10.16(R4OUT) ; port Bootloader_RESET_3V3
NetJP15_2: JP15.2 U10.17(R3OUT)
NetR34_1: R119.2 ; port LPUART_TX
NetR59_2: U10.20(R2OUTB) ; port Bootloader_BOOT0_3V3
NetR112_2: R112.2 U11.1(Anode_(VCC2))
NetR113_1: R113.1 U11.5(SD)
NetR114_1: R114.1 R116.1 U12.3(A2)
NetR117_1: R117.1 R118.1 R119.1 U12.2(A1)

Not connected (* = marked no-connect by the designer): CN9 1 4 9; U10 8(R5IN) 11(T3OUT) 15(R5OUT) 18(R2OUT) 19(R1OUT) 21(R1OUTB)*; U11 2(Cathode)

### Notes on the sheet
- USART
- (near CN9) RXD
- (near CN9) RTS
- (near CN9) DSR
- (near CN9) TXD
- (near CN9) CTS
- PG11
- IRDA
- (near R158) PG8
- Note:
  TFDU6300 (U11) is not populated
  on boards manufactured starting from
  middle 2016 (schematic and board revision C02)
- PG7
- PB7
- PB6
- PG12

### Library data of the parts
C61-C65 = CAP: as C134 on sheet IO_Expandor
C66 C68-C70 = CAP: as C141 on sheet MCU2
C67 C71 = Cap Pol1: Polarized Capacitor (Radial); Value: 100pF; Ordered by: Subcon; ECCN_US/EU: NA
CN9 = DB9: Ordered by: Subcon; Comments: DB9 USART; ECCN_US/EU: NA
JP15 = Header 3X2: Header, 3-Pin, Dual row; ECCN_US/EU: NA; Ordered by: Subcon
R93 R112-R118 = Res1: as R108 on sheet LCD_Glass
R119 R158 = Res1: as R231 on sheet IO_Expandor
U10 = ST3241: Ordered by: ST; ECCN_US/EU: EAR99/NEC; Ref St: 9176312
U11 = TFDU4300: Manuf_1: Vishay; Ordered by: Subcon; ECCN_US/EU: EAR99/NEC; Fitted or not fitted: NO
U12 = SN74LVC2T45DCUT: as U24 on sheet ST_LINK

## Sheet SWP_SmartCard_NFC.SchDoc: SWP_SmartCard_NFC
size A4; DocumentNumber: 21; Revision: C-02; SheetNumber: 21; SheetTotal: 26; Project: STM32L476G-EVAL
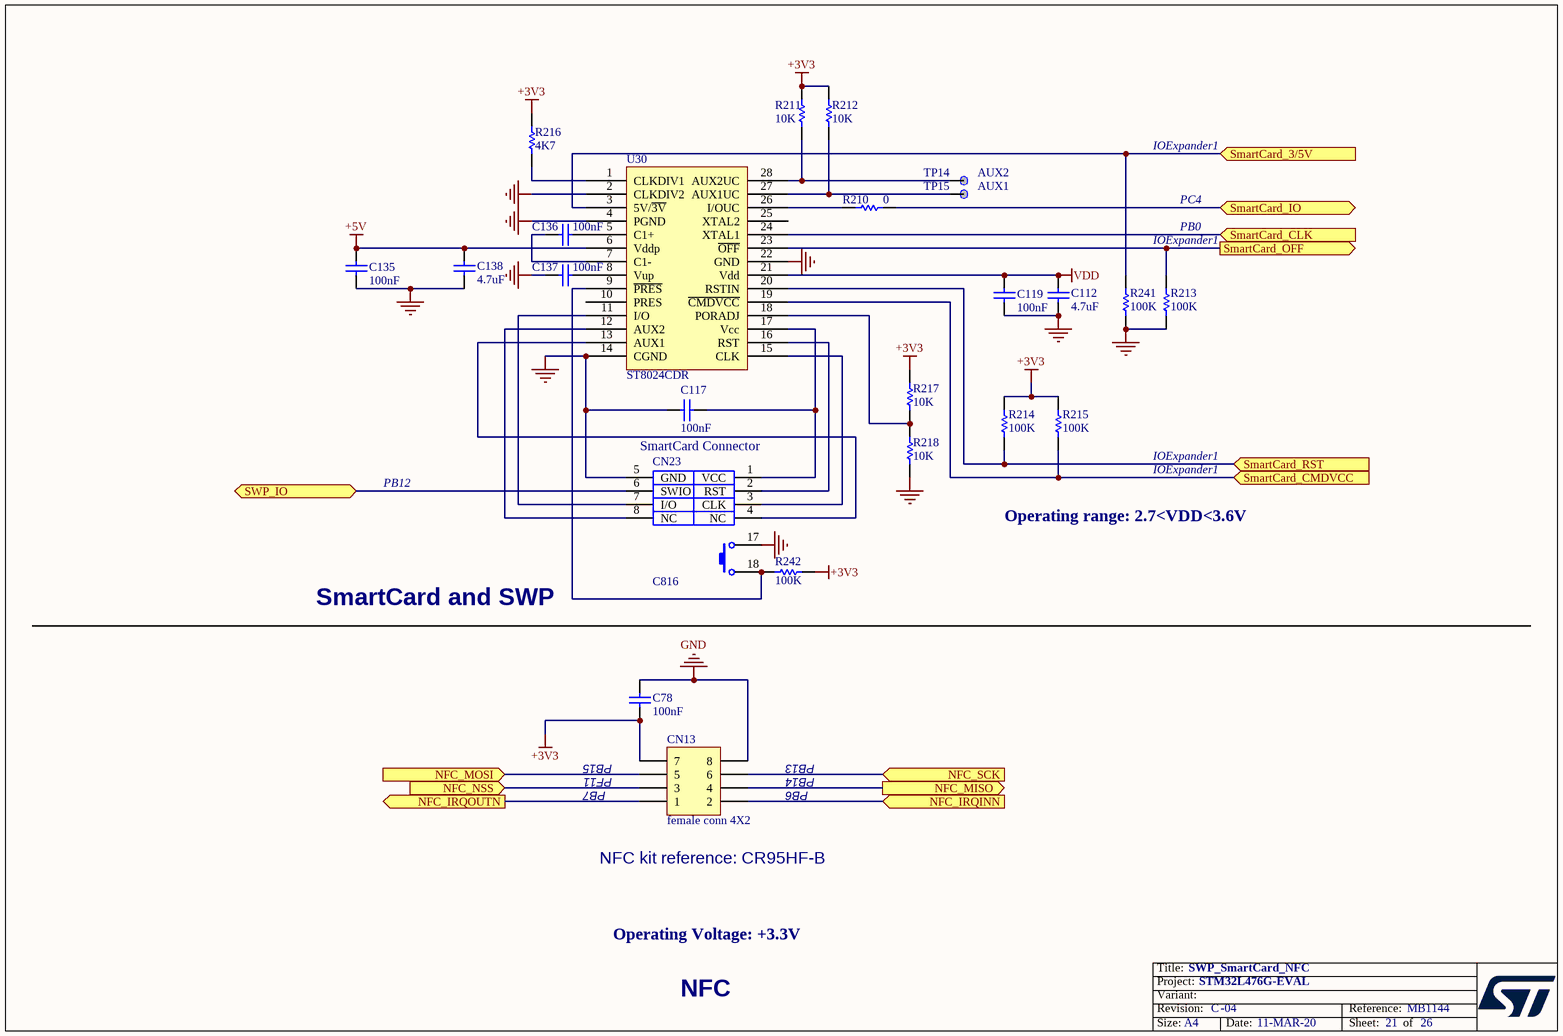
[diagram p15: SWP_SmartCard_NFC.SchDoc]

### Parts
C78  100nF  [0402C]
C112  4.7uF  [0603C]
C117  100nF  [0402C]
C119  100nF  [0402C]
C135  100nF  [0402C]
C136  100nF  [0402C]
C137  100nF  [0402C]
C138  4.7uF  [0603C]
CN13  female conn 4X2  [HDR_2X4_2R54_N]
CN23  C816  [sam_c816]
R210  0  [0603R]
R211  10K  [0402R]
R212  10K  [0402R]
R213  100K  [0402R]
R214  100K  [0402R]
R215  100K  [0402R]
R216  4K7  [0402R]
R217  10K  [0402R]
R218  10K  [0402R]
R241  100K  [0402R]
R242  100K  [0402R]
TP14  TP Name: AUX2  [TP]  (hidden comment: [N/A])
TP15  TP Name: AUX1  [TP]  (hidden comment: [N/A])
U30  ST8024CDR  [SOIC28W_1R27_17R9X10R325]

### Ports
NFC_IRQINN (in), NFC_IRQOUTN (out), NFC_MISO (out), NFC_MOSI (in), NFC_NSS (in), NFC_SCK (in), SmartCard_3/5V (in), SmartCard_CLK (in), SmartCard_CMDVCC (in), SmartCard_IO (bidir), SmartCard_OFF (out), SmartCard_RST (in), SWP_IO (bidir)

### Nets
+3V3: C78.2 CN13.7 R211.1 R212.1 R214.1 R215.1 R216.1 R217.1 R242.1
+5V: C135.1 C138.1 U30.6(Vddp)
GND: C78.1 C112.2 C117.1 C119.2 C135.2 C137.2 C138.2 CN13.8 CN23.5(GND) CN23.17 R213.2 R218.2 R241.2 U30.2(CLKDIV2) U30.4(PGND) U30.14(CGND) U30.22(GND)
VDD: C112.1 C119.1 U30.21(Vdd)
PF11: CN13.3 ; port NFC_NSS
NetC117_2: C117.2 CN23.1(VCC) U30.17(Vcc)
NetC136_1: C136.1 U30.7(C1-)
NetC136_2: C136.2 U30.5(C1+)
NetC137_1: C137.1 U30.8(Vup)
NetCN11_16: CN13.4 ; port NFC_MISO
NetCN11_18: CN13.6 ; port NFC_SCK
NetCN11_20: CN23.6(SWIO) ; port SWP_IO
NetCN11_26: CN13.5 ; port NFC_MOSI
NetCN13_1: CN13.1 ; port NFC_IRQOUTN
NetCN13_2: CN13.2 ; port NFC_IRQINN
NetCN23_2: CN23.2(RST) U30.16(RST)
NetCN23_3: CN23.3(CLK) U30.15(CLK)
NetCN23_4: CN23.4(NC) U30.13(AUX1)
NetCN23_7: CN23.7(I/O) U30.11(I/O)
NetCN23_8: CN23.8(NC) U30.12(AUX2)
NetCN23_18: CN23.18 R242.2 U30.9(~{PRES})
NetR107_1: U30.24(XTAL1) ; port SmartCard_CLK
NetR143_1: R210.2 ; port SmartCard_IO
NetR210_1: R210.1 U30.26(I/OUC)
NetR211_2: R211.2 TP14.1 U30.28(AUX2UC)
NetR212_2: R212.2 TP15.1 U30.27(AUX1UC)
NetR213_1: R213.1 U30.23(~{OFF}) ; port SmartCard_OFF
NetR214_2: R214.2 U30.20(RSTIN) ; port SmartCard_RST
NetR215_2: R215.2 U30.19(~{CMDVCC}) ; port SmartCard_CMDVCC
NetR216_2: R216.2 U30.1(CLKDIV1)
NetR217_2: R217.2 R218.1 U30.18(PORADJ)
NetR241_1: R241.1 U30.3(5V/~{3V}) ; port SmartCard_3/5V

Not connected (* = marked no-connect by the designer): U30 10(PRES) 25(XTAL2)

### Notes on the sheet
- IOExpander1
- PB0
- PC4
- PB12
- (near CN23) SmartCard Connector
- Operating range: 2.7<VDD<3.6V
- SmartCard and SWP
- PB7
- PB15
- PF11
- PB6
- PB14
- PB13
- (near CN13) NFC kit reference: CR95HF-B
- Operating Voltage: +3.3V
- NFC

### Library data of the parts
C78 = CAP: as C141 on sheet MCU2
C112 C138 = Cap: as C132 on sheet IO_Expandor
C117 C119 C135-C137 = CAP: as C134 on sheet IO_Expandor
CN13 = female conn 4X2: female conn 4X2 4-Pin, Dual row; Ordered by: Subcon; ECCN_US/EU: NA; Comments: NFC connector
CN23 = Smart_card_CN: Ordered by: Subcon; Comments: Smartcard "GSM file and SWP" conenctor; ECCN_US/EU: NA; Assembly: with ST smartcard 8000080
R210-R218 R241 R242 = Res1: as R108 on sheet LCD_Glass
TP14 TP15 = TP: as TP7 on sheet MCU2
U30 = ST8024CTR: Ordered by: ST; ECCN_US/EU: EAR99/NEC; Ref St: 9177802

## Sheet STPMS2&PT100.SchDoc: STPMS2&PT100
size A4; DocumentNumber: 20; Revision: C-02; SheetNumber: 20; SheetTotal: 26; Project: STM32L476G-EVAL
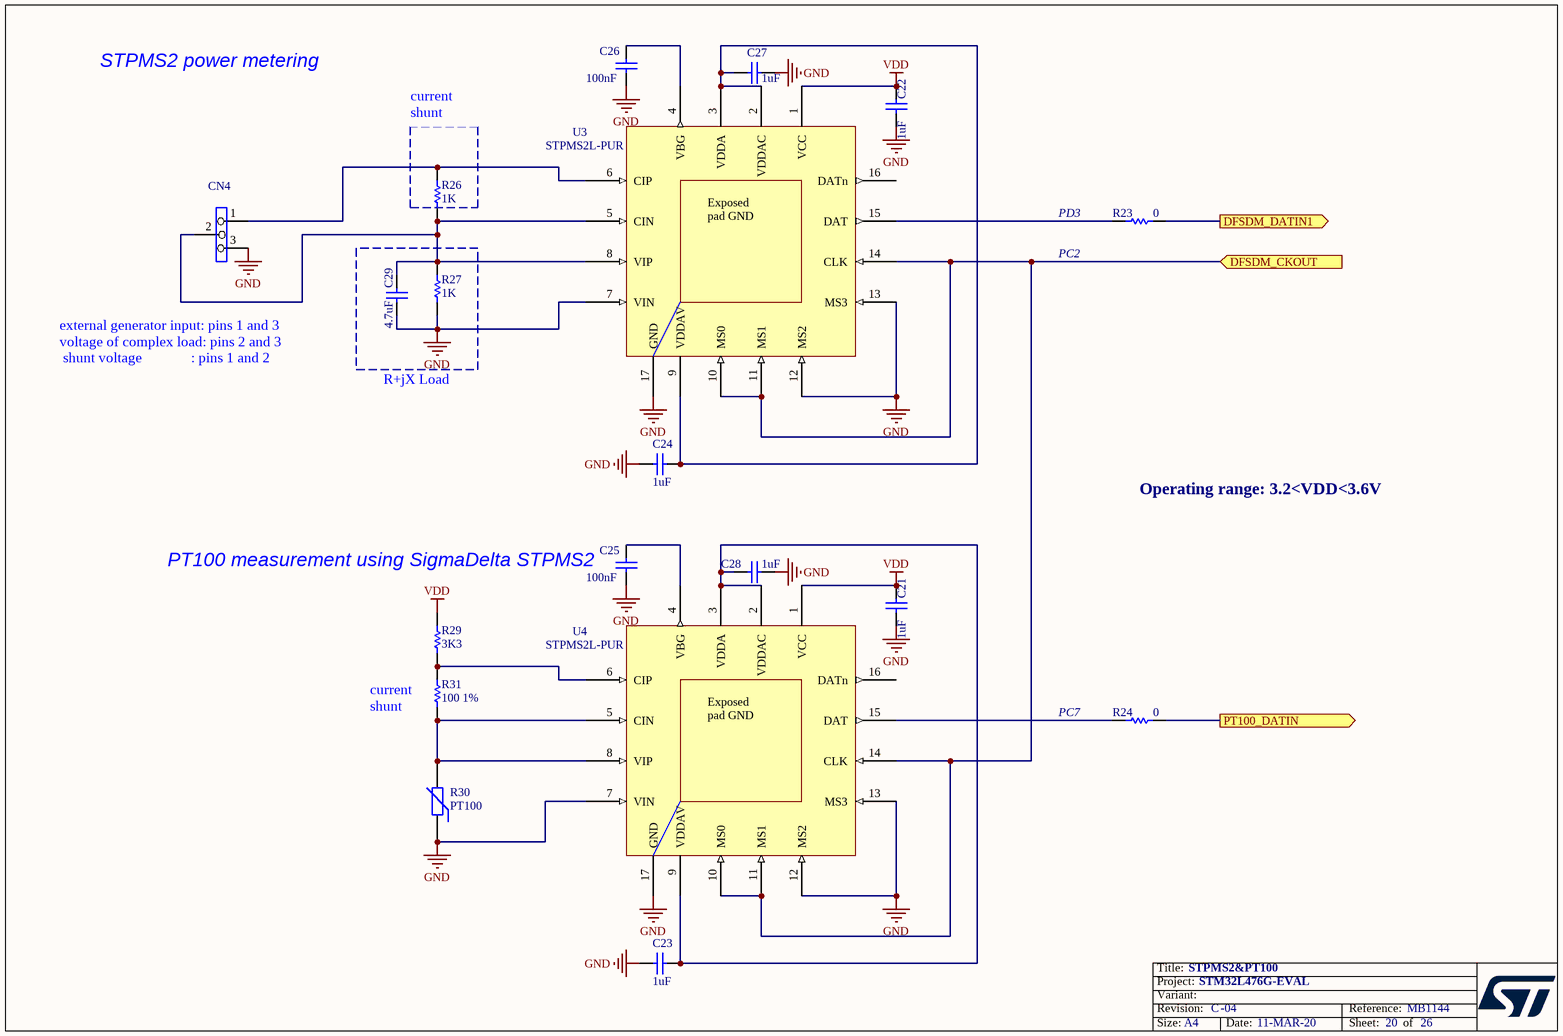
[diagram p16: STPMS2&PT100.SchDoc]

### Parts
C21  1uF  [0603C]
C22  1uF  [0603C]
C23  1uF  [0603C]
C24  1uF  [0603C]
C25  100nF  [0402C]
C26  100nF  [0402C]
C27  1uF  [0603C]
C28  1uF  [0603C]
C29  4.7uF  [0603C]
CN4  Header 3X1  [SIP3]  (value not drawn)
R23  0  [0603R]
R24  0  [0603R]
R26  1K  [0402R]
R27  1K  [0402R]
R29  3K3  [0402R]
R30  PT100  [HDR_1X2_1R27]
R31  100 1%  [0603R]
U3  STPMS2L-PUR  [QFN16_0R65_4X4]
U4  STPMS2L-PUR  [QFN16_0R65_4X4]

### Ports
DFSDM_CKOUT (in), DFSDM_DATIN1 (out), PT100_DATIN (out)

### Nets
GND: C21.2 C22.2 C23.1 C24.1 C25.1 C26.1 C27.2 C28.2 C29.2 CN4.3 R27.2 R30.1 U3.7(VIN) U3.12(MS2) U3.13(MS3) U3.17(GND) U4.7(VIN) U4.12(MS2) U4.13(MS3) U4.17(GND)
VDD: C21.1 C22.1 R29.1 U3.1(VCC) U4.1(VCC)
PD3: R23.1 ; port DFSDM_DATIN1
NetC23_2: C23.2 C28.1 U4.2(VDDAC) U4.3(VDDA) U4.9(VDDAV)
NetC24_2: C24.2 C27.1 U3.2(VDDAC) U3.3(VDDA) U3.9(VDDAV)
NetC25_2: C25.2 U4.4(VBG)
NetC26_2: C26.2 U3.4(VBG)
NetC29_1: C29.1 CN4.2 R26.2 R27.1 U3.5(CIN) U3.8(VIP)
NetCN4_1: CN4.1 R26.1 U3.6(CIP)
NetCN11_28: U3.10(MS0) U3.11(MS1) U3.14(CLK) U4.10(MS0) U4.11(MS1) U4.14(CLK) ; port DFSDM_CKOUT
NetR23_2: R23.2 U3.15(DAT)
NetR24_1: R24.1 ; port PT100_DATIN
NetR24_2: R24.2 U4.15(DAT)
NetR29_2: R29.2 R31.1 U4.6(CIP)
NetR30_2: R30.2 R31.2 U4.5(CIN) U4.8(VIP)

Not connected (* = marked no-connect by the designer): U3 16(DATn); U4 16(DATn)

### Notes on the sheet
- STPMS2 power metering
- current shunt
- (near R23) PD3
- PC2
- external generator input: pins 1 and 3
  voltage of complex load: pins 2 and 3
  shunt voltage              : pins 1 and 2
- R+jX Load
- PT100 measurement using SigmaDelta STPMS2
- Operating range: 3.2<VDD<3.6V
- (near R31) current shunt
- (near R24) PC7

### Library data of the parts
C21-C24 C27-C29 = CAP: as C58 on sheet MCU2
C25 C26 = Cap: as C132 on sheet IO_Expandor
CN4 = Jumper3: Ordered by: Subcon; ECCN_US/EU: NA
R23 R24 = res1: as R107 on sheet LCD_Glass
R26 R27 = Res1: as R268 on sheet ST_LINK
R29 R31 = Res1: as R108 on sheet LCD_Glass
R30 = PT100: Varistor (Voltage-Sensitive Resistor); ECCN_US/EU: NA; Ordered by: Subcon
U3 U4 = STPMS2: STM sigmaDelta modulator; Ordered by: ST; ECCN_US/EU: EAR99/NEC; Ref St: 9177717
